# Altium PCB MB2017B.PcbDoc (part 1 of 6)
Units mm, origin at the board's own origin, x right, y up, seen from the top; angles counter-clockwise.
Board outline 148.19 x 169.19 mm, 4 copper layers (Top Layer, Mid Layer 1, Mid Layer 2, Bottom Layer), stack 1.498 mm thick; 458 components, 208 nets, 1223 pads, 6162 vias.
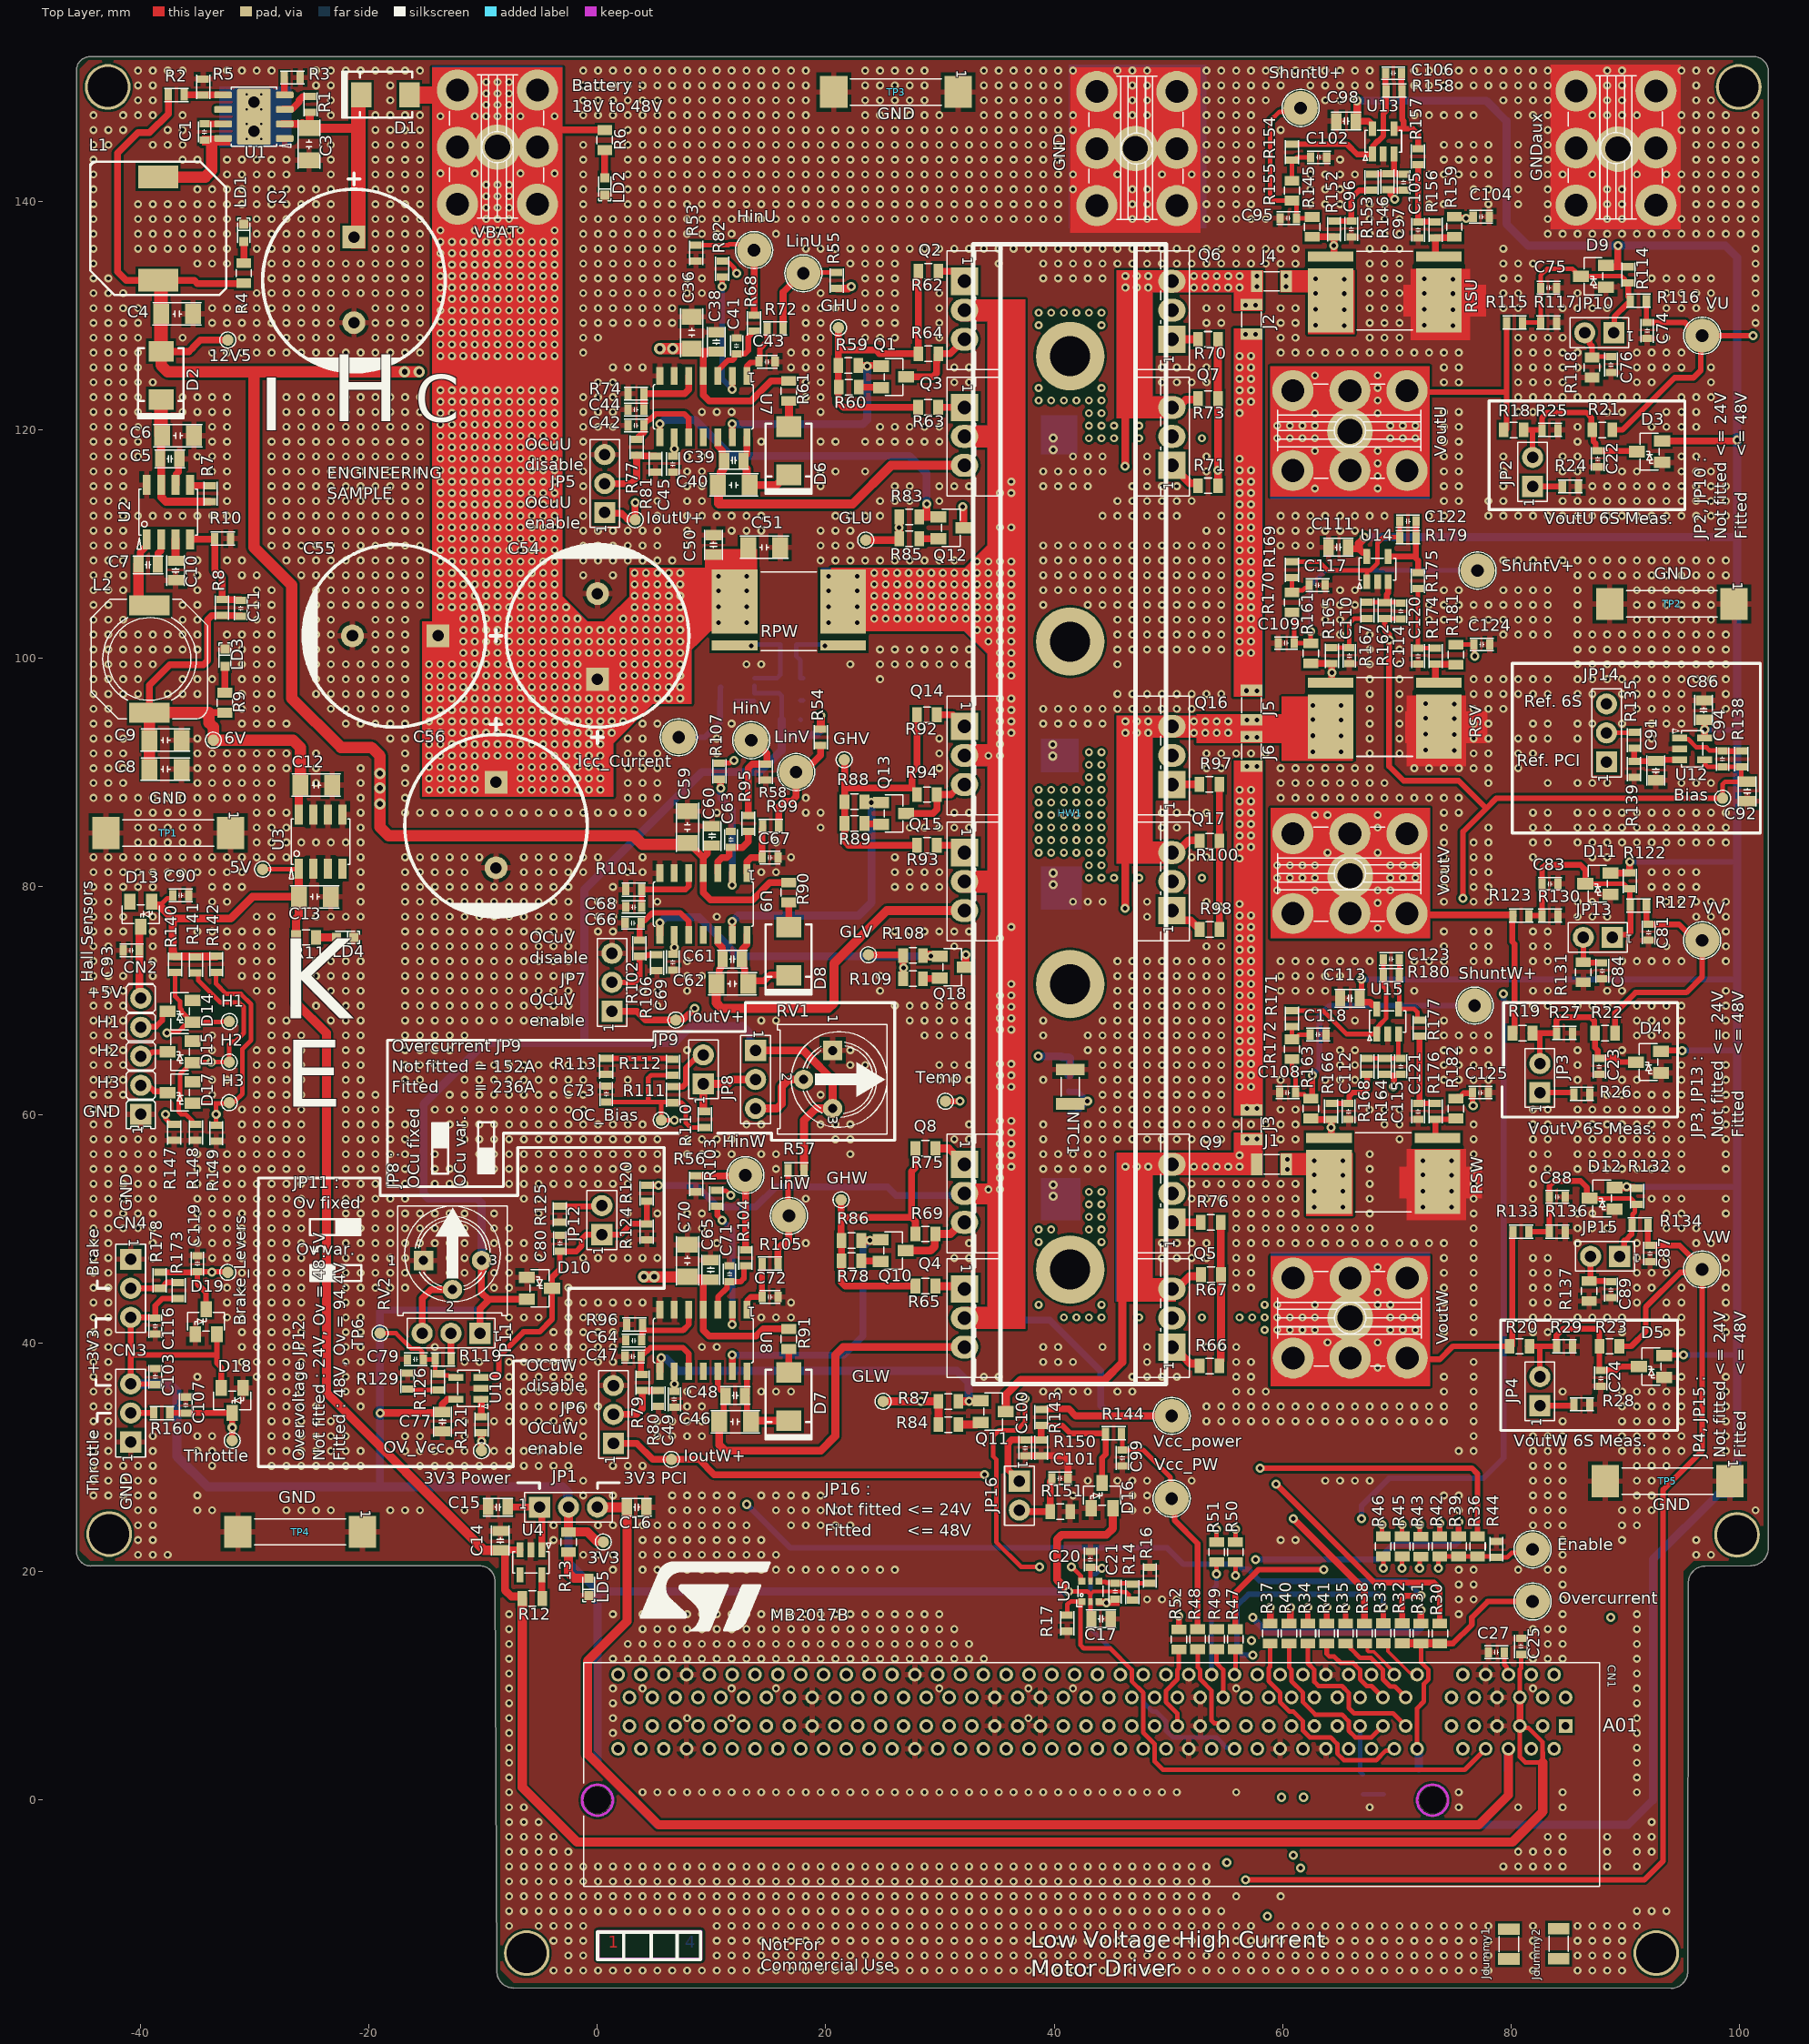
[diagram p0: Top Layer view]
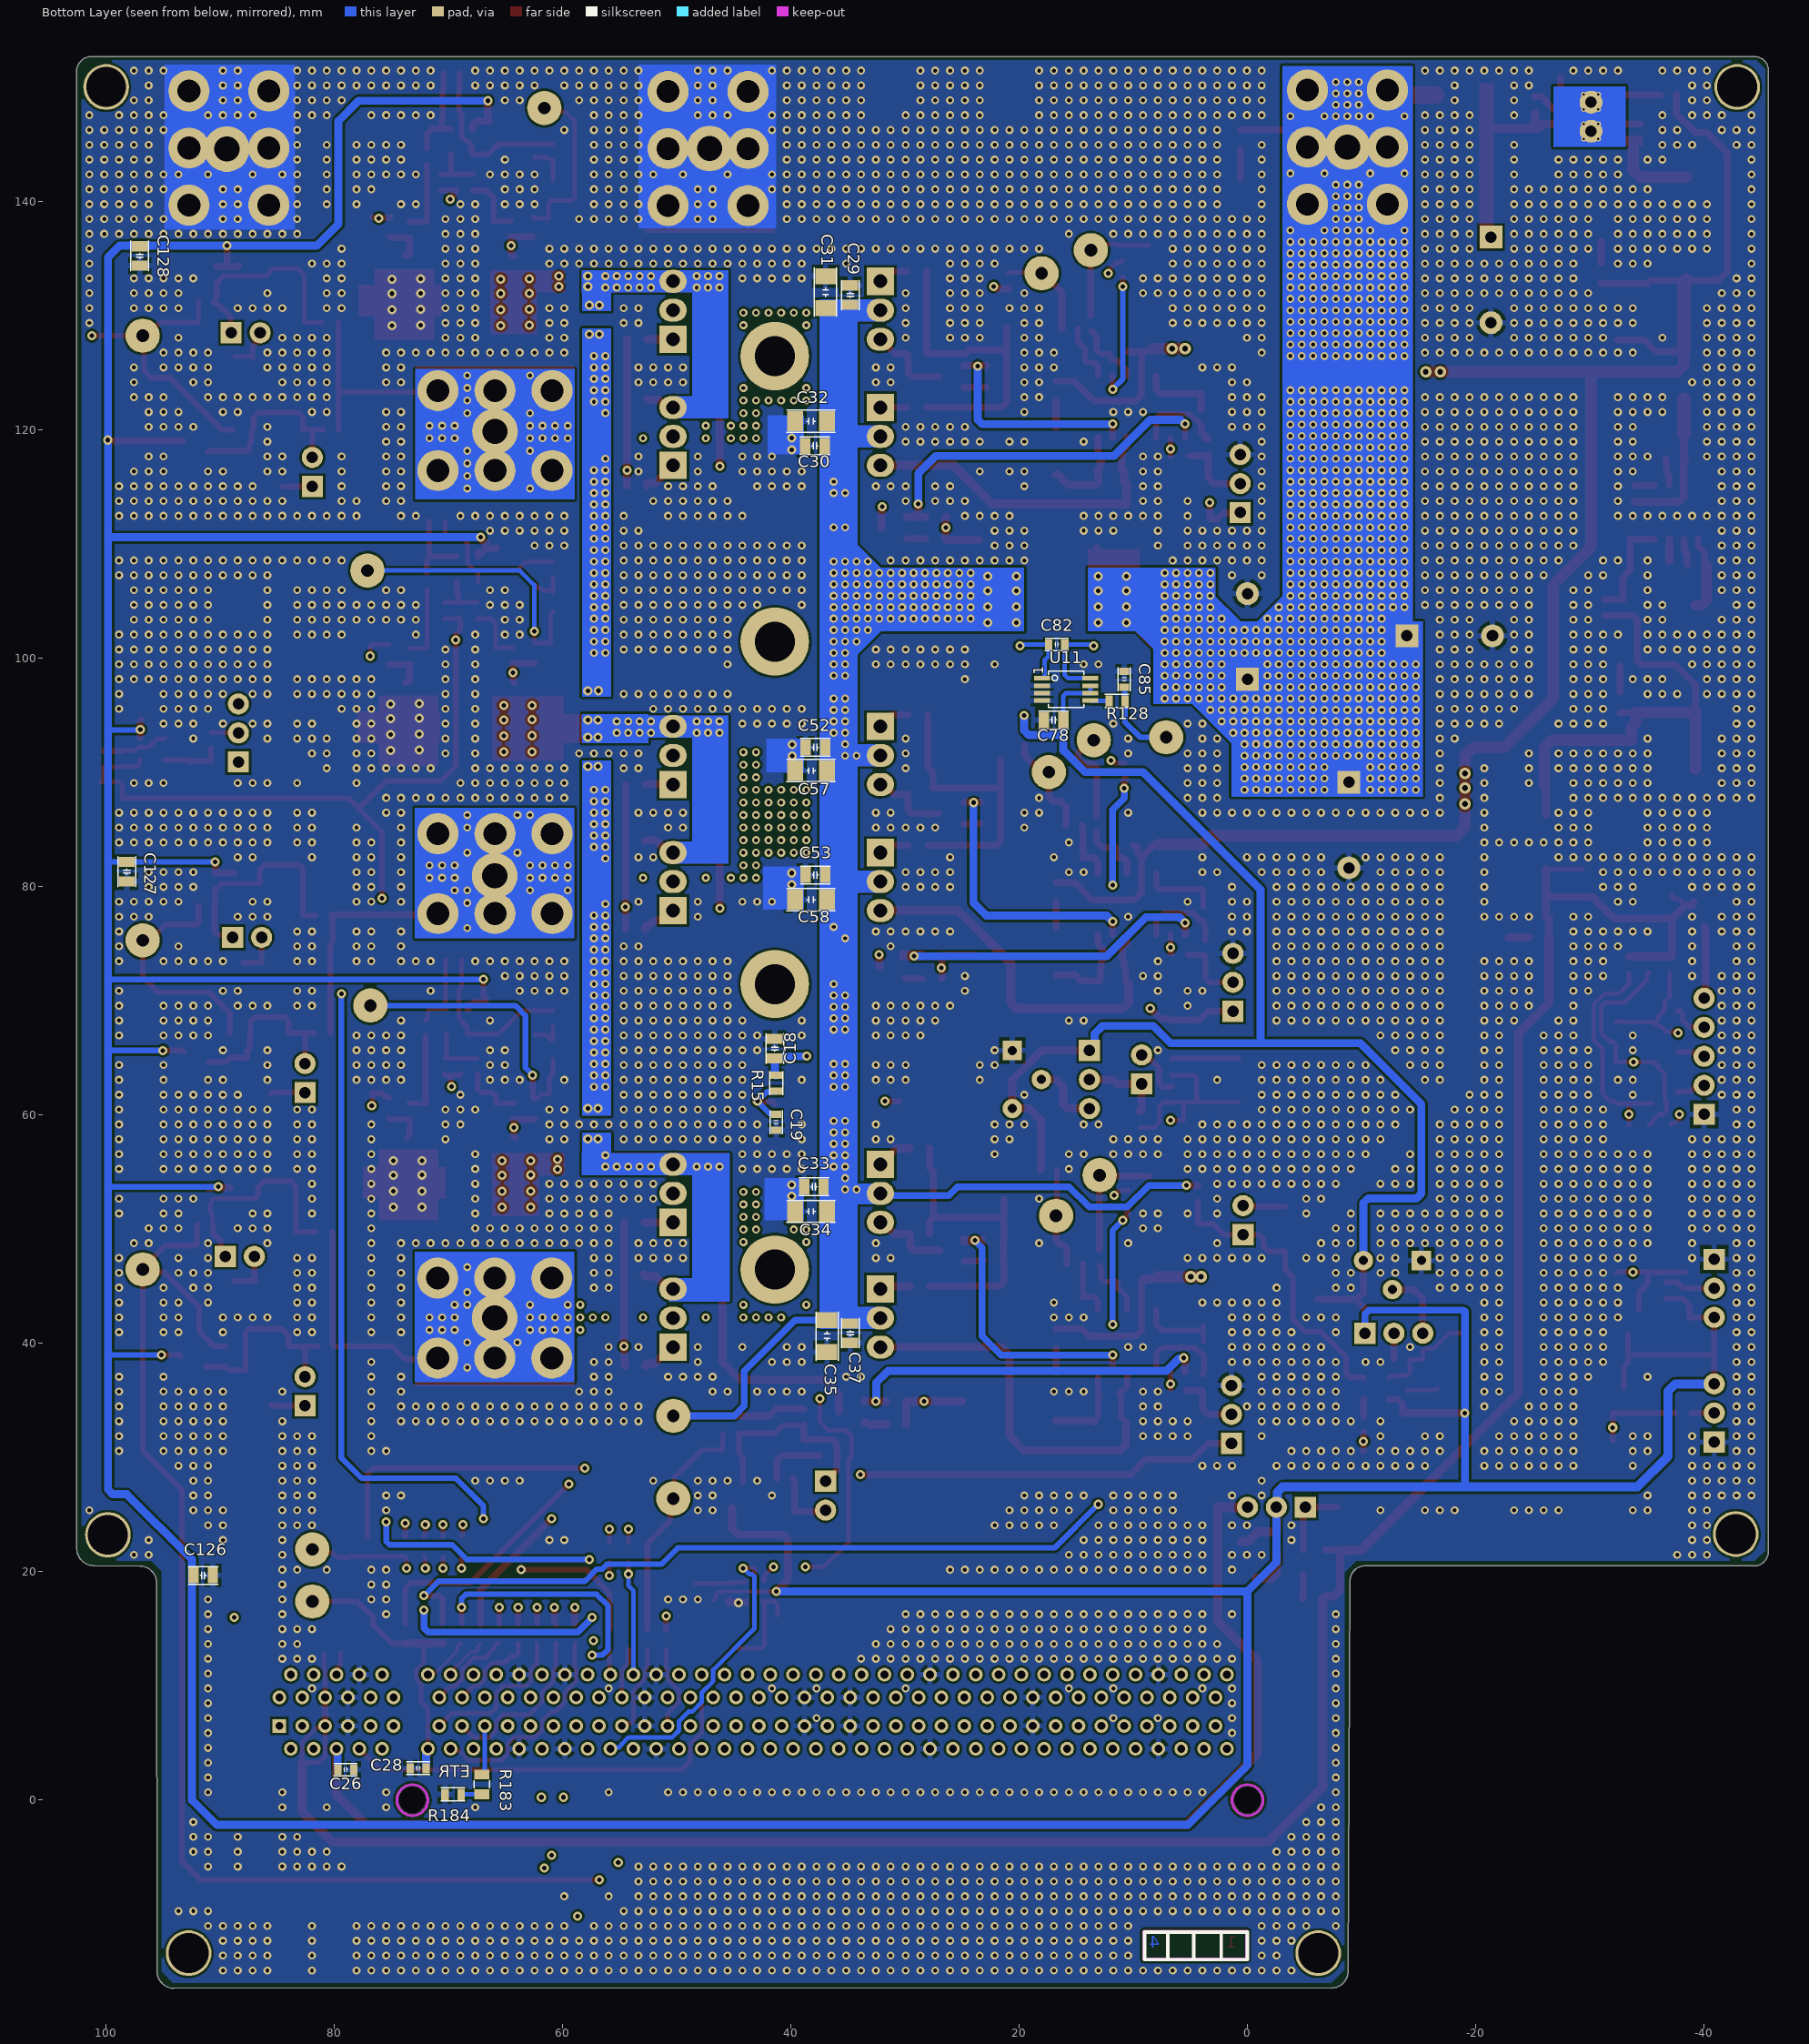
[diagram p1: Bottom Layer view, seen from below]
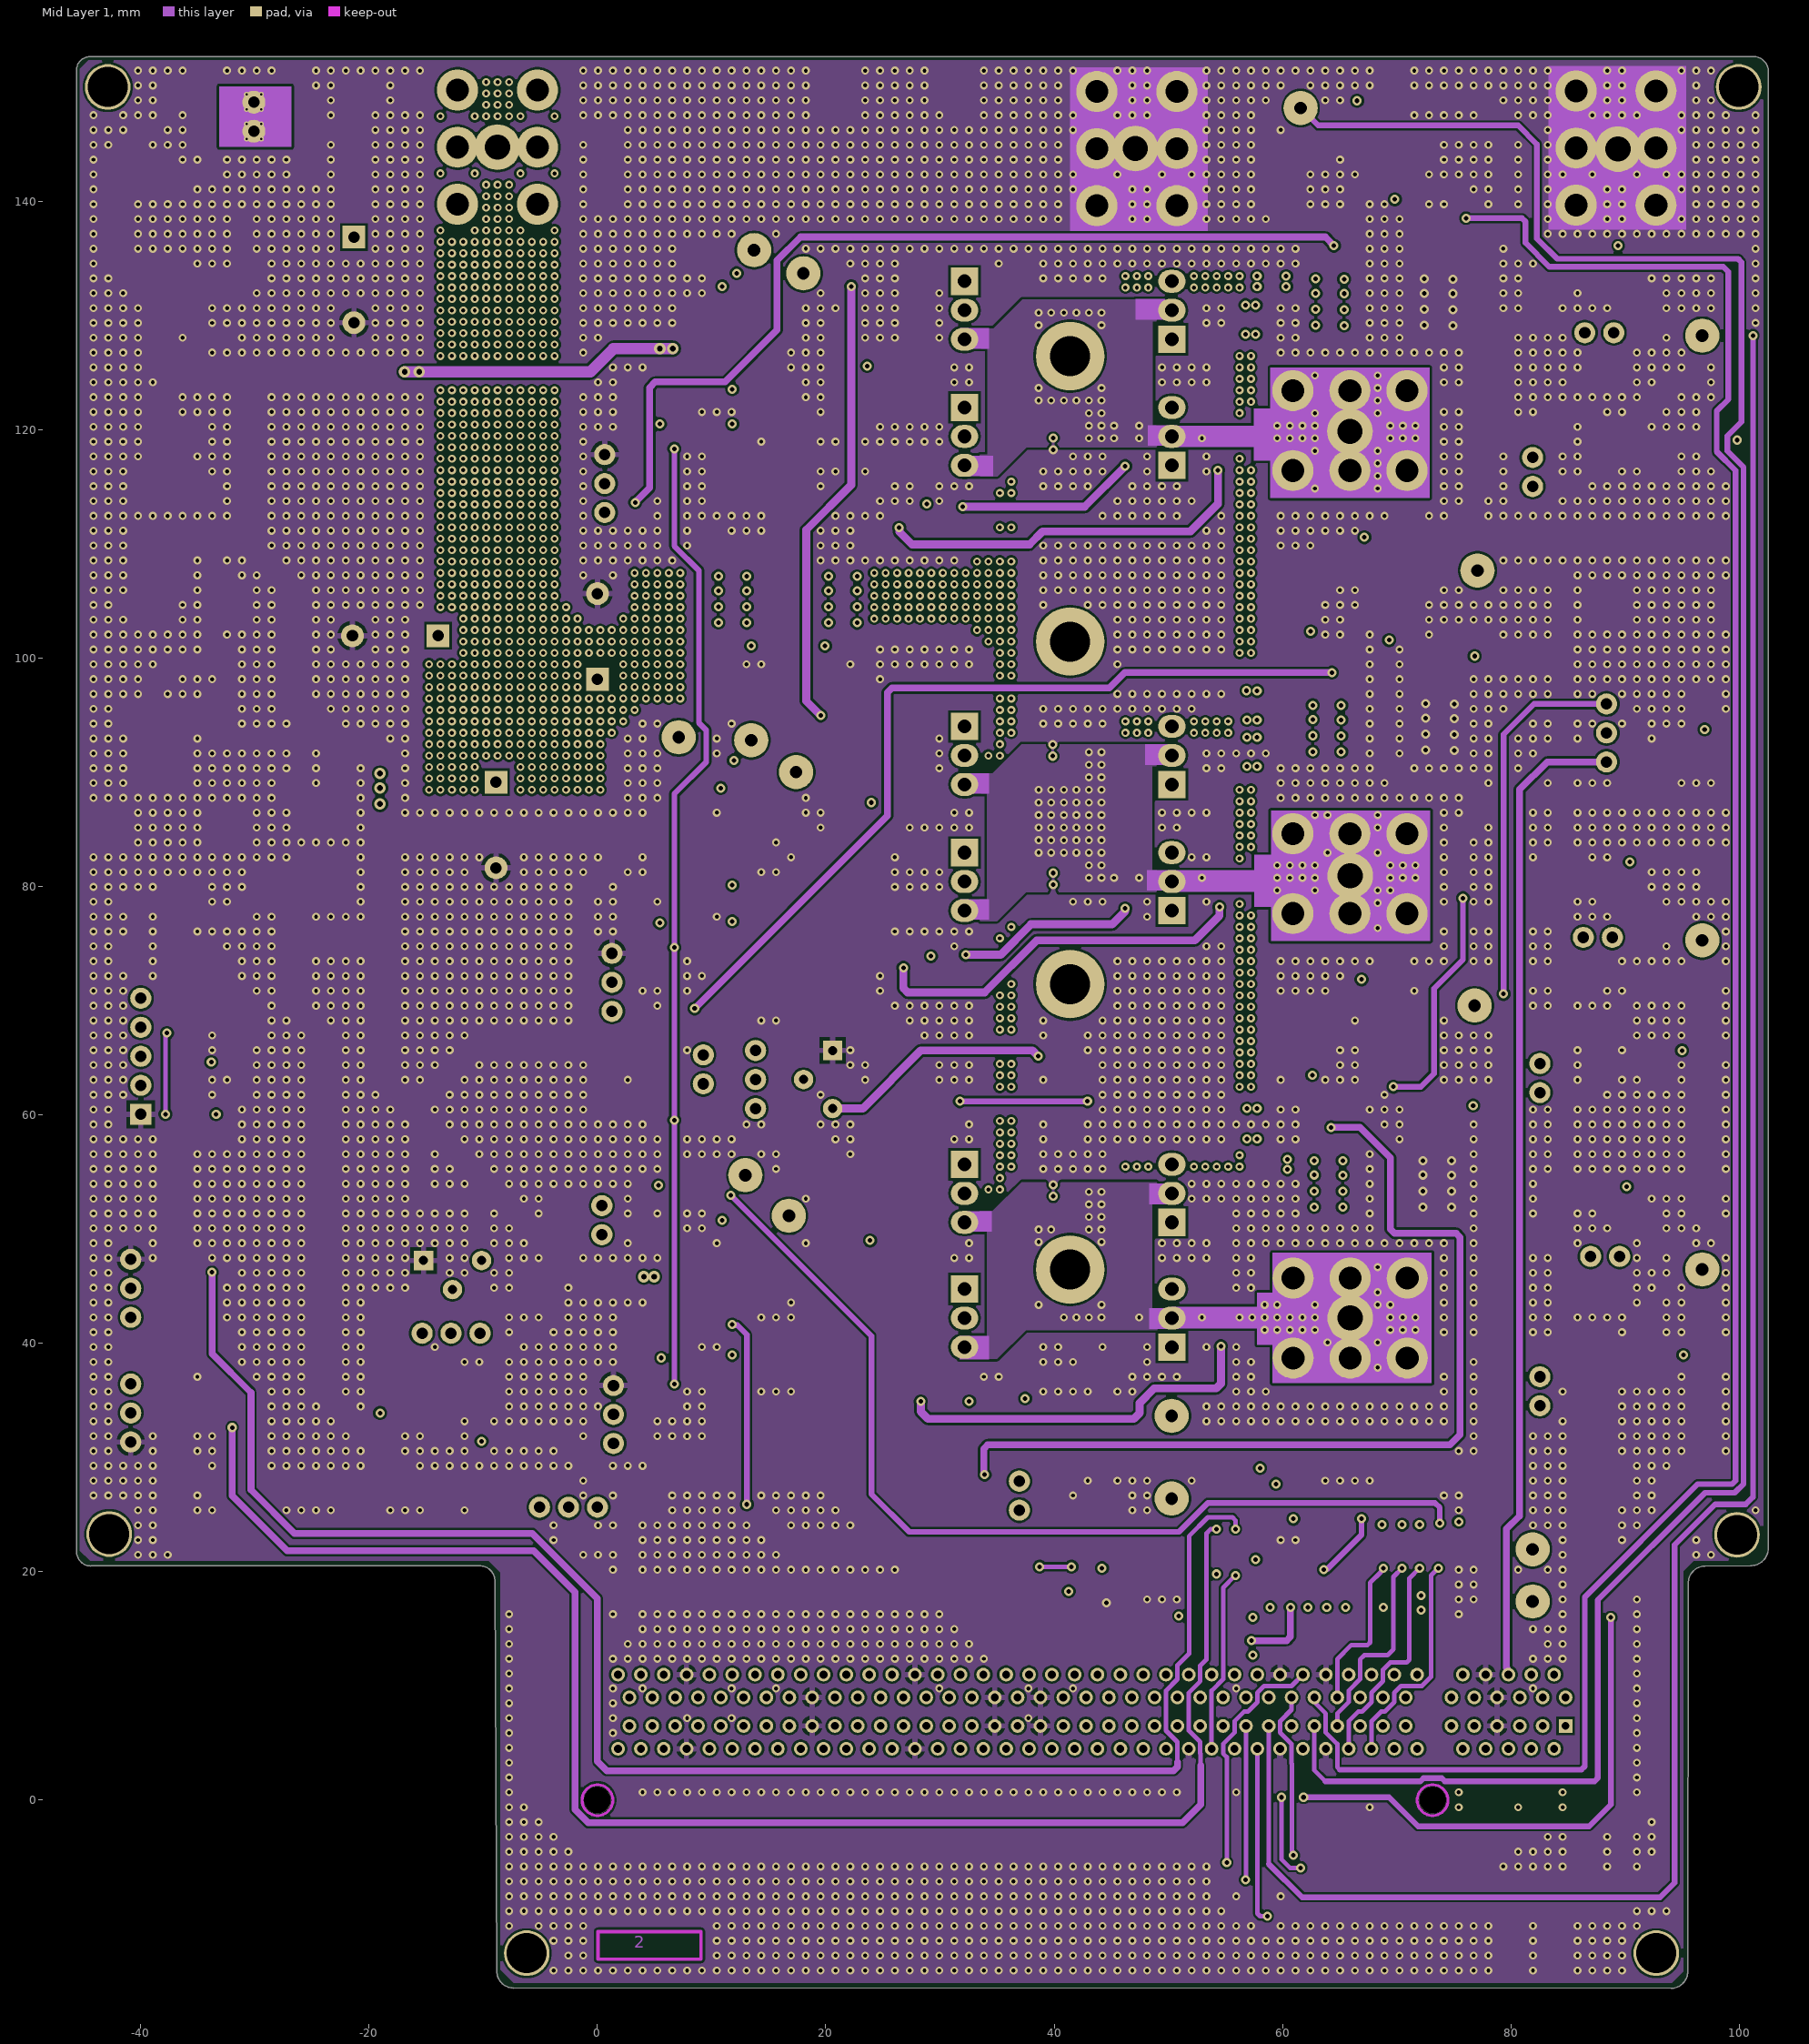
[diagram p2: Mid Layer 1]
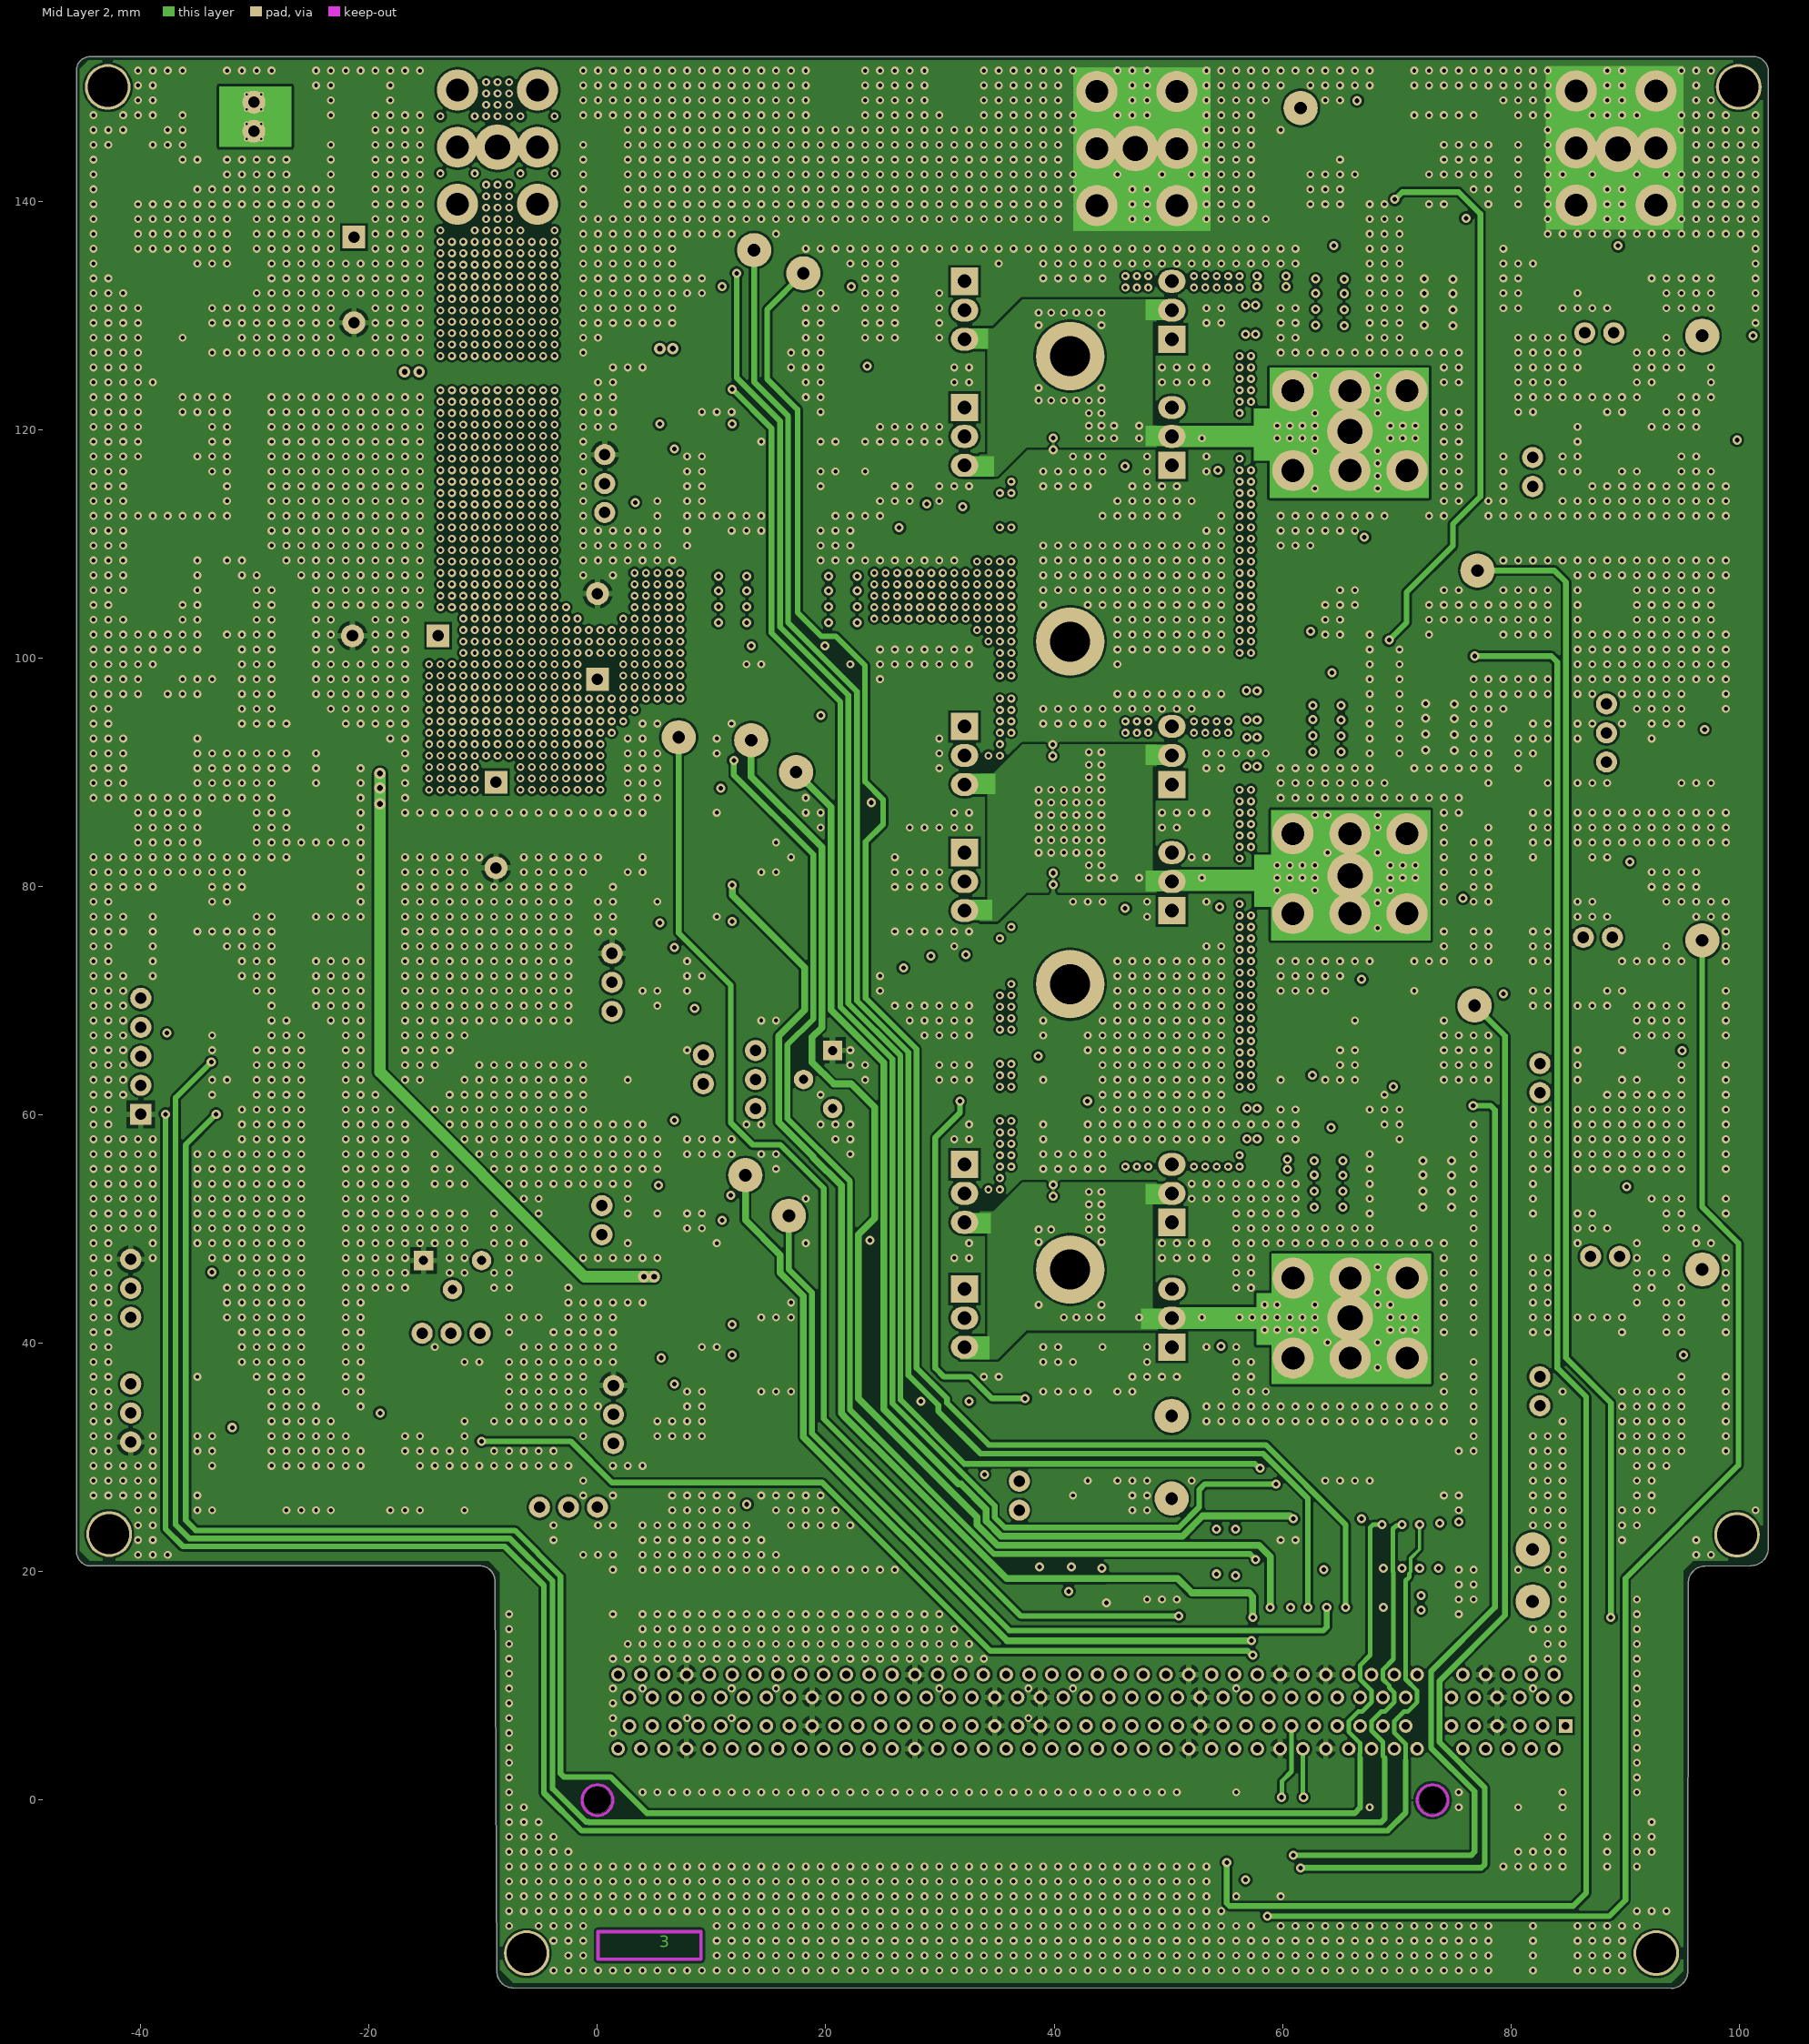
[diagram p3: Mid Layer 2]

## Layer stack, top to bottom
Top Solder: solder mask 0.015, Solder Resist, Dk 3.5
Top Layer: signal copper 0.07
Dielectric 2: prepreg 0.229, PP-006, Dk 4.1
Mid Layer 1: signal copper 0.07
Dielectric 1: dielectric 0.76, FR-4, Dk 4.8
Mid Layer 2: signal copper 0.07
Dielectric 3: prepreg 0.229, PP-006, Dk 4.1
Bottom Layer: signal copper 0.07
Bottom Solder: solder mask 0.015, Solder Resist, Dk 3.5

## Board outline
-10.318,20.524 cw(c-10.318,19.195) -8.988,19.195 -8.814,-14.986 ccw(c-7.339,-14.986) -7.339,-16.46 -7.339,-16.457 94.04,-16.48 ccw(c94.04,-15.018) 95.502,-15.018 95.553,19.022 cw(c97.026,19.022) 97.026,20.496 101.012,20.532 ccw(c101.012,22.083) 102.563,22.083 102.564,151.41 ccw(c101.265,151.41) 101.265,152.709 101.167,152.709 -44.481,152.694 ccw(c-44.481,151.544) -45.631,151.544 -45.631,21.762 ccw(c-44.377,21.762) -44.377,20.508 -44.362,20.524

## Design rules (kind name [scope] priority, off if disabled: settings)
Clearance [All] p1: gap=0.2 ignorepadtopadclearanceinfootprint=TRUE except(0: Arc-Text Arc-Hole Track-Text Track-Hole SMDPad-Text SMDPad-Hole THPad-Text THPad-Hole Via-Text Via-Hole Fill-Text Fill-Hole Poly-Text Poly-Hole Region-Text Region-Hole Text-Text Text-Hole)
ComponentClearance [All] p1: gap=0.2 collisioncheckmode=3 verticalgap=0.2 showdistances=FALSE
Height [All] p1: minheight=0 maxheight=80 prefheight=12.7
HoleSize [All] p1: absolutevalues=TRUE maxlimit=10 minlimit=0.025 maxpercent=80.000 minpercent=20.000
MinimumSolderMaskSliver [All] p1: minsoldermaskwidth=0.1
PlaneConnect [All] p1: planeconnectstyle=Relief reliefexpansion=0.508 reliefentries=4 reliefconductorwidth=0.5 reliefairgap=0.3
PolygonConnect PolygonConnect_via [IsVia] p1: connectstyle=Direct reliefconductorwidth=0.254 reliefentries=4 polygonreliefangle="90 Angle" airgapwidth=0.254
PolygonConnect [All] p2: connectstyle=Relief reliefconductorwidth=0.5 reliefentries=4 polygonreliefangle="90 Angle" airgapwidth=0.3
RoutingVias [All] p1: holewidth=0.4 width=0.8 viastyle="Through Hole" minholewidth=0.3 minwidth=0.8 maxholewidth=0.5 maxwidth=1
SilkToSilkClearance [All] p1: silktosilkclearance=0.05
SilkToSolderMaskClearance [IsPad] p1: minsilkscreentomaskgap=0.2 clearancetoexposedcopper=TRUE
SolderMaskExpansion [All] p1: expansion=0.102 istentingtop=FALSE
UnRoutedNet [All] p1: checkbadconnections=TRUE
Width [All] p1: maxlimit=10 minlimit=0.2 preferedwidth=0.4 minimp=50.000000 maximp=50.000000 favimp=50.000000
22 further rules are at their usual default settings.

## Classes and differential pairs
component class U_Sensors: Bias Brake_Levers C74 C75 C76 C77 C78 C79 C80 C81 C82 C83 C84 C85 C86 C87 C88 C89 C90 C91 C92 C93 C94 C95 C96 C97 C98 C99 C100 C101 C102 C103 C104 C105 C106 C107 C108 C109 C110 C111 C112 C113 C114 C115 C116 C117 C118 C119 C120 C121 C122 C123 C124 C125 CN2 CN3 CN4 D9 D10 D11 D12 D13 D14 D15 D16 D17 D18 D19 H1 H2 H3 Icc_Current JP10 JP11 JP12 JP13 JP14 JP15 JP16 OV_Vcc R114 R115 R116 R117 R118 R119 R120 R121 R122 R123 R124 R125 R126 R127 R128 R129 R130 R131 R132 R133 R134 R135 R136 R137 R138 R139 R140 R141 R142 R143 R144 R145 R146 R147 R148 R149 R150 R151 R152 R153 R154 R155 R156 R157 R158 R159 R160 R161 R162 R163 R164 R165 R166 R167 R168 R169 R170 R171 R172 R173 R174 R175 R176 R177 R178 R179 R180 R181 R182 RV2 ShuntU+ ShuntV+ ShuntW+ Throttle TP6 U10 U11 U12 U13 U14 U15 Vcc_PW VU VV VW
component class U_Sensors_2: C17 C18 C19 C20 C21 C22 C23 C24 D3 D4 D5 JP2 JP3 JP4 NTC1 R14 R15 R16 R17 R18 R19 R20 R21 R22 R23 R24 R25 R26 R27 R28 R29 Temp U5
component class U_Power_Stage: C29 C30 C31 C32 C33 C34 C35 C36 C37 C38 C39 C40 C41 C42 C43 C44 C45 C46 C47 C48 C49 C50 C51 C52 C53 C54 C55 C56 C57 C58 C59 C60 C61 C62 C63 C64 C65 C66 C67 C68 C69 C70 C71 C72 C73 D6 D7 D8 GHU GHV GHW GLU GLV GLW HinU HinV HinW HW1 IoutU+ IoutV+ IoutW+ J1 J2 J3 J4 J5 J6 Jdummy1 Jdummy2 JP5 JP6 JP7 JP8 JP9 LinU LinV LinW OC_Bias Q1 Q2 Q3 Q4 Q5 Q6 Q7 Q8 Q9 Q10 Q11 Q12 Q13 Q14 Q15 Q16 Q17 Q18 R59 R60 R61 R62 R63 R64 R65 R66 R67 R68 R69 R70 R71 R72 R73 R74 R75 R76 R77 R78 R79 R80 R81 R82 R83 R84 R85 R86 R87 R88 R89 R90 R91 R92 R93 R94 R95 R96 R97 R98 R99 R100 R101 R102 R103 R104 R105 R106 R107 R108 R109 R110 R111 R112 R113 RPW RSU RSV RSW RV1 TP1 TP2 TP3 TP4 TP5 U7 U8 U9 Vcc_power VoutU VoutV VoutW
component class U_Power_Supplies: 3V3 5V 6V 12V5 C1 C2 C3 C4 C5 C6 C7 C8 C9 C10 C11 C12 C13 C14 C15 C16 C126 C127 C128 D1 D2 GND GNDaux JP1 L1 L2 LD1 LD2 LD3 LD4 LD5 R1 R2 R3 R4 R5 R6 R7 R8 R9 R10 R11 R12 R13 U1 U2 U3 U4 VBAT
component class U_PCI_Connector: C25 C26 C27 C28 CN1 Enable Overcurrent R30 R31 R32 R33 R34 R35 R36 R37 R38 R39 R40 R41 R42 R43 R44 R45 R46 R47 R48 R49 R50 R51 R52 R53 R54 R55 R56 R57 R58 R183 R184

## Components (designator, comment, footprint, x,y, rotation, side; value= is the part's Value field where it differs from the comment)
3V3 "Test Point" TP_SMD_1MM 0.508,22.606 r180 top value="Test Point 1mm"
5V "Test Point" TP_SMD_1MM -29.337,81.534 r90 top value="Test Point 1mm"
6V "Test Point" TP_SMD_1MM -33.655,92.837 r90 top value="Test Point 1mm"
12V5 "Test Point" TP_SMD_1MM -32.385,127.889 r90 top value="Test Point 1mm"
Bias "Test Point" TP_SMD_1MM 98.552,87.757 r270 top value="Test Point 1mm"
Brake_Levers "Test Point" TP_SMD_1MM -32.385,46.228 r90 top value="Test Point 1mm"
C1 "Capacitor" C0603_H0P8 -34.417,146.115 r90 top value=2.2nF
C2 "Cap_POL_TANA" CPOL_TDK_B41858C9227M000_H25 -21.336,136.906 r270 top value=220uF
C3 "Capacitor" C1206_H1P6 -25.273,145.037 r90 top value=1uF
C4 "Capacitor" C1206_H1P6 -36.827,130.175 r180 top value=47uF
C5 "Capacitor" C0805_H0P85 -37.465,117.475 r180 top value=1uF
C6 "Capacitor" C1206_H1P6 -36.757,119.511 r180 top value=10uF
C7 "Capacitor" C0805_H0P85 -39.37,108.204 r0 top value=100nF
C8 "Capacitor" C1206_H1P6 -37.843,90.297 r180 top value=10uF
C9 "Capacitor" C1206_H1P6 -37.843,92.837 r180 top value=22uF
C10 "Capacitor" C0805_H0P85 -36.957,107.696 r90 top value=1uF
C11 "Capacitor" C0603 -31.242,104.394 r270 top value=10pF
C12 "Capacitor" C1206_H1P6 -24.635,88.9 r180 top value=10uF
C13 "Capacitor" C1206_H1P6 -24.762,79.121 r180 top value=10uF
C14 "Capacitor" C0805_H0P85 -8.509,22.733 r270 top value=1uF
C15 "Capacitor" C0805_H0P85 -8.724,25.654 r0 top value=1uF
C16 "Capacitor" C0805_H0P85 3.429,25.654 r180 top value=1uF
C17 "Capacitor" C0805_H0P85 44.108,15.875 r180 top value=1uF
C18 "Capacitor" C0805_H0P85 41.402,65.825 r270 bottom value=1uF
C19 "Capacitor" C0603 41.275,59.371 r90 bottom value=4.7nF
C20 "Capacitor" C0603 43.18,21.082 r270 top value=4.7nF
C21 "Capacitor" C0603 45.339,18.288 r90 top value=100nF
C22 "Capacitor" C0603 87.63,117.475 r90 top value=10pF
C23 "Capacitor" C0603 87.757,64.262 r90 top value=10pF
C24 "Capacitor" C0603 87.884,36.957 r90 top value=10pF
C25 "Capacitor" C0603 80.899,13.462 r90 top value=100nF
C26 "Capacitor" C0603 78.994,2.667 r180 bottom value=100nF
C27 "Capacitor" C0603 78.74,12.954 r180 top value=100nF
C28 "Capacitor" C0603 72.644,2.794 r0 bottom value=100nF
C29 "Capacitor" C0805 34.798,131.826 r90 bottom value=100nF
C30 "Capacitor" C0805 37.885,118.618 r0 bottom value=100nF
C31 "Capacitor" C1206_H1P6 36.957,132.08 r90 bottom value=1uF
C32 "Capacitor" C1206_H1P6 38.227,120.777 r0 bottom value=1uF
C33 "Capacitor" C0805 37.973,53.721 r0 bottom value=100nF
C34 "Capacitor" C1206_H1P6 38.227,51.562 r0 bottom value=1uF
C35 "Capacitor" C1206_H1P6 36.83,40.64 r270 bottom value=1uF
C36 "Capacitor" C1206_H1P25 8.255,128.527 r270 top value=4.7uF
C37 "Capacitor" C0805 34.798,40.894 r270 bottom value=100nF
C38 "Capacitor" C0805_H0P85 10.414,127.723 r270 top value=100nF
C39 "Capacitor" C0805_H0P85 11.938,117.348 r0 top value=100nF
C40 "Capacitor" C1206_H1P15 11.938,115.189 r0 top value=1uF
C41 "Capacitor" C0603_H0P8 12.192,127.381 r270 top value=100pF
C42 "Capacitor" C0603 3.364,120.396 r180 top value=10nF
C43 "Capacitor" C0603_H0P8 14.859,125.984 r180 top value=100pF
C44 "Capacitor" C0603 3.364,121.793 r0 top value=100nF
C45 "Capacitor" C0603 6.604,117.029 r90 top value=100nF
C46 "Capacitor" C1206_H1P15 12.065,33.147 r0 top value=1uF
C47 "Capacitor" C0603 3.113,38.862 r180 top value=10nF
C48 "Capacitor" C0805_H0P85 12.065,35.433 r0 top value=100nF
C49 "Capacitor" C0603 6.731,35.117 r90 top value=100nF
C50 "Capacitor" C0805 10.16,109.943 r90 top value=100nF
C51 "Capacitor" C1206_H1P6 14.608,109.728 r0 top value=1uF
C52 "Capacitor" C0805 37.846,92.202 r0 bottom value=100nF
C53 "Capacitor" C0805 37.846,81.026 r0 bottom value=100nF
C54 "Cap_POL_TANA" CPOL_TDK_B41858C9227M000_H25 0,98.171 r90 top value=220uF
C55 "Cap_POL_TANA" CPOL_TDK_B41858C9227M000_H25 -13.97,101.981 r180 top value=220uF
C56 "Cap_POL_TANA" CPOL_TDK_B41858C9227M000_H25 -8.89,89.154 r270 top value=220uF
C57 "Capacitor" C1206_H1P6 38.227,90.17 r0 bottom value=1uF
C58 "Capacitor" C1206_H1P6 38.227,78.867 r0 bottom value=1uF
C59 "Capacitor" C1206_H1P25 7.874,85.214 r270 top value=4.7uF
C60 "Capacitor" C0805_H0P85 10.033,84.455 r270 top value=100nF
C61 "Capacitor" C0805_H0P85 11.811,73.66 r0 top value=100nF
C62 "Capacitor" C1206_H1P15 11.814,71.501 r0 top value=1uF
C63 "Capacitor" C0603_H0P8 11.684,84.136 r270 top value=100pF
C64 "Capacitor" C0603 3.175,40.259 r0 top value=100nF
C65 "Capacitor" C0805_H0P85 9.906,46.443 r270 top value=100nF
C66 "Capacitor" C0603 3.113,76.835 r180 top value=10nF
C67 "Capacitor" C0603_H0P8 15.113,82.55 r180 top value=100pF
C68 "Capacitor" C0603 3.175,78.232 r0 top value=100nF
C69 "Capacitor" C0603 6.604,73.406 r90 top value=100nF
C70 "Capacitor" C1206_H1P25 7.874,47.244 r270 top value=4.7uF
C71 "Capacitor" C0603_H0P8 11.557,46.101 r270 top value=100pF
C72 "Capacitor" C0603_H0P8 15.113,44.069 r180 top value=100pF
C73 "Capacitor" C0603 0.762,61.849 r270 top value=100nF
C74 "Capacitor" C0603 91.948,128.716 r90 top value=100pF
C75 "Capacitor" C0603 83.312,132.461 r180 top value=33nF
C76 "Capacitor" C0603 88.773,125.73 r90 top value=33nF
C77 "Capacitor" C0805_H0P85 -13.589,33.147 r90 top value=1uF
C78 "Capacitor" C0805_H0P85 16.979,94.615 r180 bottom value=1uF
C79 "Capacitor" C0603 -15.94,38.608 r180 top value=100nF
C80 "Capacitor" C0603 -3.302,48.768 r270 top value=1nF
C81 "Capacitor" C0603 92.075,76.008 r90 top value=100pF
C82 "Capacitor" C0603 16.699,101.219 r180 bottom value=10nF
C83 "Capacitor" C0603 83.439,80.264 r180 top value=33nF
C84 "Capacitor" C0603 88.011,72.644 r90 top value=33nF
C85 "Capacitor" C0603 10.795,98.171 r270 bottom value=10nF
C86 "Capacitor" C0805_H0P85 96.901,95.465 r270 top value=1uF
C87 "Capacitor" C0603 92.202,47.879 r90 top value=100pF
C88 "Capacitor" C0603 84.074,52.832 r180 top value=33nF
C89 "Capacitor" C0603 88.773,44.704 r90 top value=33nF
C90 "Capacitor" C0603 -36.511,79.248 r0 top value=100nF
C91 "Capacitor" C0805_H0P85 92.71,90.17 r90 top value=1uF
C92 "Capacitor" C0805_H0P85 100.711,88.353 r90 top value=1uF
C93 "Capacitor" C0603 -40.832,74.422 r180 top value=100nF
C94 "Capacitor" C0603 98.552,91.186 r270 top value=10nF
C95 "Capacitor" C0603 60.514,138.557 r180 top value=1nF
C96 "Capacitor" C0603 66.04,137.603 r270 top value=1nF
C97 "Capacitor" C0603 70.612,141.705 r270 top value=10pF
C98 "Capacitor" C0805_H0P85 65.571,147.066 r0 top value=1uF
C99 "Capacitor" C0603 45.974,29.972 r90 top value=100pF
C100 "Capacitor" C0603 37.465,30.861 r90 top value=10nF
C101 "Capacitor" C0603 40.513,28.194 r180 top value=10nF
C102 "Capacitor" C0603 63.181,143.891 r180 top value=100pF
C103 "Capacitor" C0603 -38.735,37.084 r90 top value=100nF
C104 "Capacitor" C0603 77.408,138.684 r0 top value=1nF
C105 "Capacitor" C0603 71.882,137.541 r90 top value=1nF
C106 "Capacitor" C0603 69.723,151.257 r0 top value=10pF
C107 "Capacitor" C0603 -36.068,34.609 r90 top value=100nF
C108 "Capacitor" C0603 60.452,61.976 r180 top value=1nF
C109 "Capacitor" C0603 60.325,101.346 r180 top value=1nF
C110 "Capacitor" C0603 65.859,100.23 r270 top value=1nF
C111 "Capacitor" C0805_H0P85 64.897,109.728 r0 top value=1uF
C112 "Capacitor" C0603 65.786,60.325 r270 top value=1nF
C113 "Capacitor" C0805_H0P85 65.913,70.231 r0 top value=1uF
C114 "Capacitor" C0603 70.358,104.14 r270 top value=10pF
C115 "Capacitor" C0603 70.358,64.262 r270 top value=10pF
C116 "Capacitor" C0603 -38.735,41.529 r270 top value=100nF
C117 "Capacitor" C0603 63.054,106.426 r180 top value=100pF
C118 "Capacitor" C0603 63.119,67.056 r180 top value=100pF
C119 "Capacitor" C0603 -35.052,46.99 r90 top value=100nF
C120 "Capacitor" C0603 71.882,100.203 r90 top value=1nF
C121 "Capacitor" C0603 71.882,60.325 r90 top value=1nF
C122 "Capacitor" C0603 70.993,112.014 r0 top value=10pF
C123 "Capacitor" C0603 69.531,73.66 r0 top value=10pF
C124 "Capacitor" C0603 77.47,101.219 r180 top value=1nF
C125 "Capacitor" C0603 77.343,61.976 r180 top value=1nF
C126 "Capacitor" C0805_H0P85 91.479,19.685 r0 bottom value=1uF
C127 "Capacitor" C0805_H0P85 98.171,81.319 r90 bottom value=1uF
C128 "Capacitor" C0805_H0P85 97.028,135.255 r90 bottom value=1uF
CN1 "PCIE-164-02-X-D-RA" CON_SAMTEC_PCIE-164-02-X-D-RA 43.3,2.25 r0 top locked value=Socket_PCIE-164-02-S-D-RA
CN2 "Header 5x1" CON_SAMTEC_TSW-105-07-X-S -40.005,65.151 r90 top
CN3 "Header 3x1" CON_SAMTEC_TSW-103-07-F-S -40.894,33.909 r90 top
CN4 "Header 3x1" CON_SAMTEC_TSW-103-07-F-S -40.894,44.831 r270 top
D1 "DIODE_1K_2A" DIO_SMB_1K_2A -20.701,149.352 r0 top value=STTH2R02U
D2 "DIODE_1K_2A" DIO_SMB_1K_2A -38.227,122.682 r90 top value=STTH2R02U
D3 "DIODE_3P_DUAL_SERIES" DIO_SOT23 92.159,118.11 r90 top value=BAT54SFILM
D4 "DIODE_3P_DUAL_SERIES" DIO_SOT23 92.075,64.643 r90 top value=BAT54SFILM
D5 "DIODE_3P_DUAL_SERIES" DIO_SOT23 92.329,37.973 r90 top value=BAT54SFILM
D6 "DIODE_1K_2A" DIO_SMB_1K_2A 16.764,116.078 r90 top value=STTH2R02U
D7 "DIODE_1K_2A" DIO_SMB_1K_2A 16.764,33.245 r90 top value=STTH2R02U
D8 "DIODE_1K_2A" DIO_SMB_1K_2A 16.764,72.234 r90 top value=STTH2R02U
D9 "DIODE_3P_DUAL_SERIES" DIO_SOT23 87.249,133.477 r90 top value=BAT54SFILM
D10 "DIODE_3P_DUAL_SERIES" DIO_SOT23 -5.08,44.831 r270 top value=BAT54SFILM
D11 "DIODE_3P_DUAL_SERIES" DIO_SOT23 87.63,80.264 r90 top value=BAT54SFILM
D12 "DIODE_3P_DUAL_SERIES" DIO_SOT23 88.011,52.705 r90 top value=BAT54SFILM
D13 "DIODE_SOT23" DIO_SOT23 -40.005,77.597 r180 top value=BAT54FILM
D14 "DIODE_SOT23" DIO_SOT23 -36.576,69.088 r90 top value=BAT54FILM
D15 "DIODE_SOT23" DIO_SOT23 -36.576,65.532 r90 top value=BAT54FILM
D16 "DIODE_3P_DUAL_SERIES" DIO_SOT23 44.196,26.67 r0 top value=BAT54SFILM
D17 "DIODE_SOT23" DIO_SOT23 -36.576,61.976 r90 top value=BAT54FILM
D18 "DIODE_3P_DUAL_SERIES" DIO_SOT23 -32.004,35.009 r180 top value=BAT54SFILM
D19 "DIODE_3P_DUAL_SERIES" DIO_SOT23 -34.29,41.91 r0 top value=BAT54SFILM
Enable "Test_pin_conn_black - NOT CONNECTED" TP_PTH-1P02MM_TEST-TERMINAL_RS_101-2391_BLACK 81.915,21.971 r0 top value=20-2137
GHU "Test Point" TP_SMD_1MM 21.105,128.967 r90 top value="Test Point 1mm"
GHV "Test Point" TP_SMD_1MM 21.613,91.121 r90 top value="Test Point 1mm"
GHW "Test Point" TP_SMD_1MM 21.336,52.578 r90 top value="Test Point 1mm"
GLU "Test Point" TP_SMD_1MM 23.495,110.363 r90 top value="Test Point 1mm"
GLV "Test Point" TP_SMD_1MM 23.729,74.037 r90 top value="Test Point 1mm"
GLW "Test Point" TP_SMD_1MM 25.019,34.925 r90 top value="Test Point 1mm"
GND "CON_M4_SNAP_IN_THR_KEYSTONE_7798" CON_KEYSTONE_M4-SNAP_7798 47.244,144.653 r90 top value="TERM SCREW M4 PCB 30A"
GNDaux "CON_M4_SNAP_IN_THR_KEYSTONE_7798" CON_KEYSTONE_M4-SNAP_7798 89.225,144.7 r90 top value="TERM SCREW M4 PCB 30A"
H1 "Test Point" TP_SMD_1MM -32.258,68.199 r90 top value="Test Point 1mm"
H2 "Test Point" TP_SMD_1MM -32.258,64.643 r180 top value="Test Point 1mm"
H3 "Test Point" TP_SMD_1MM -32.258,61.087 r180 top value="Test Point 1mm"
HinU "Test_pin_conn_black - NOT CONNECTED" TP_PTH-1P02MM_TEST-TERMINAL_RS_101-2391_BLACK 13.716,135.763 r0 top value=20-2137
HinV "Test_pin_conn_black - NOT CONNECTED" TP_PTH-1P02MM_TEST-TERMINAL_RS_101-2391_BLACK 13.462,92.837 r0 top value=20-2137
HinW "Test_pin_conn_black - NOT CONNECTED" TP_PTH-1P02MM_TEST-TERMINAL_RS_101-2391_BLACK 12.954,54.737 r0 top value=20-2137
HW1 "SK664100SA" MISC_Fischer_Elektronik_SK664100SA 41.402,46.473 r90 top
Icc_Current "Test_pin_conn_black - NOT CONNECTED" TP_PTH-1P02MM_TEST-TERMINAL_RS_101-2391_BLACK 7.112,93.091 r90 top value=20-2137
IoutU+ "Test Point" TP_SMD_1MM 3.302,112.141 r90 top value="Test Point 1mm"
IoutV+ "Test Point" TP_SMD_1MM 6.858,68.326 r90 top value="Test Point 1mm"
IoutW+ "Test Point" TP_SMD_1MM 6.477,29.845 r90 top value="Test Point 1mm"
J1 "Resistor" MISC_JUMPER_1206_H0P55 59.048,55.688 r180 top value=TLRZ2BTTD
J2 "Resistor" MISC_JUMPER_1206_H0P55 57.3,129.699 r90 top value=TLRZ2BTTD
J3 "Resistor" MISC_JUMPER_1206_H0P55 57.3,59.147 r90 top value=TLRZ2BTTD
J4 "Resistor" MISC_JUMPER_1206_H0P55 59.048,133.031 r180 top value=TLRZ2BTTD
J5 "Resistor" MISC_JUMPER_1206_H0P55 57.3,95.917 r270 top value=TLRZ2BTTD
J6 "Resistor" MISC_JUMPER_1206_H0P55 57.3,91.853 r90 top value=TLRZ2BTTD
Jdummy1 "Resistor" MISC_JUMPER_1206_H0P55 79.829,-12.608 r270 top value=TLRZ2BTTD
Jdummy2 "Resistor" MISC_JUMPER_1206_H0P55 84.201,-12.573 r270 top value=TLRZ2BTTD
JP1 "Jumper_Header 3x1 Fitted 1-2" CON_SAMTEC_TSW-103-07-F-S -2.54,25.654 r0 top value="Header 3x1"
JP2 "Jumper_Header 2x1" CON_SAMTEC_TSW-102-07-G-S 81.915,116.332 r90 top value="Header 2x1"
JP3 "Jumper_Header 2x1" CON_SAMTEC_TSW-102-07-G-S 82.55,63.246 r90 top value="Header 2x1"
JP4 "Jumper_Header 2x1" CON_SAMTEC_TSW-102-07-G-S 82.55,35.814 r90 top value="Header 2x1"
JP5 "Jumper_Header 3x1 Fitted 1-2" CON_SAMTEC_TSW-103-07-F-S 0.635,115.316 r90 top value="Header 3x1"
JP6 "Jumper_Header 3x1 Fitted 1-2" CON_SAMTEC_TSW-103-07-F-S 1.397,33.782 r90 top value="Header 3x1"
JP7 "Jumper_Header 3x1 Fitted 1-2" CON_SAMTEC_TSW-103-07-F-S 1.27,71.628 r90 top value="Header 3x1"
JP8 "Jumper_Header 3x1 Fitted 1-2" CON_SAMTEC_TSW-103-07-F-S 13.843,63.119 r270 top value="Header 3x1"
JP9 "Jumper_Header 2x1" CON_SAMTEC_TSW-102-07-G-S 9.271,64.008 r90 top value="Header 2x1"
JP10 "Jumper_Header 2x1" CON_SAMTEC_TSW-102-07-G-S 87.757,128.524 r180 top value="Header 2x1"
JP11 "Jumper_Header 3x1 Fitted 1-2" CON_SAMTEC_TSW-103-07-F-S -12.827,40.894 r180 top value="Header 3x1"
JP12 "Jumper_Header 2x1" CON_SAMTEC_TSW-102-07-G-S 0.381,50.8 r90 top value="Header 2x1"
JP13 "Jumper_Header 2x1" CON_SAMTEC_TSW-102-07-G-S 87.63,75.565 r180 top value="Header 2x1"
JP14 "Jumper_Header 3x1 Fitted 1-2" CON_SAMTEC_TSW-103-07-F-S 88.392,93.472 r90 top value="Header 3x1"
JP15 "Jumper_Header 2x1" CON_SAMTEC_TSW-102-07-G-S 88.265,47.625 r180 top value="Header 2x1"
JP16 "Jumper_Header 2x1" CON_SAMTEC_TSW-102-07-G-S 36.957,26.67 r270 top value="Header 2x1"
L1 "INDUCTOR_POWER_WINDING" IND_WURTH_7447714680 -38.481,142.113 r270 top value=68uH
L2 "INDUCTOR_POWER_WINDING" IND_COILCRAFT_MSS1038T-333MLC -39.243,99.949 r0 top value=33uH
LD1 "LED_green" LED_0603_VISHAY_VLMTG1300-GS08_GREEN_1A2K_H0P8 -30.988,137.275 r90 top value=Green
LD2 "LED_red" LED_0603_VISHAY_VLMS1300-GS08_RED_1A2K_H0P8 0.635,141.339 r270 top value=Red
LD3 "LED_orange" LED_0603_VISHAY_VLMO1300-GS08_ORANGE_1A2K_H0P8 -32.639,100.064 r90 top value=Orange
LD4 "LED_red" LED_0603_VISHAY_VLMS1300-GS08_RED_1A2K_H0P8 -22.11,75.565 r0 top value=Red
LD5 "LED_blue" LED_0603_VISHAY_VLMB1300-GS08_BLUE_1A2K_H0P8 -0.762,18.669 r270 top value=Blue
LinU "Test_pin_conn_black - NOT CONNECTED" TP_PTH-1P02MM_TEST-TERMINAL_RS_101-2391_BLACK 18.034,133.731 r0 top value=20-2137
LinV "Test_pin_conn_black - NOT CONNECTED" TP_PTH-1P02MM_TEST-TERMINAL_RS_101-2391_BLACK 17.399,90.043 r0 top value=20-2137
LinW "Test_pin_conn_black - NOT CONNECTED" TP_PTH-1P02MM_TEST-TERMINAL_RS_101-2391_BLACK 16.764,51.181 r0 top value=20-2137
MB2017B "Comment" LOGO_ST 9.903,17.767 r0 top
NTC1 "MISC_NTC_NB20K00103JBA" NTC1206_AVX_NB20_H1P5 41.402,62.484 r270 top value=10K
OC_Bias "Test Point" TP_SMD_1MM 5.588,59.563 r180 top value="Test Point 1mm"
OV_Vcc "Test Point" TP_SMD_1MM -10.16,30.607 r180 top value="Test Point 1mm"
Overcurrent "Test_pin_conn_black - NOT CONNECTED" TP_PTH-1P02MM_TEST-TERMINAL_RS_101-2391_BLACK 81.915,17.399 r90 top value=20-2137
Q1 "PNP_SOT23" PNP_SOT23 25.931,124.649 r270 top value=FMMT718TA
Q2 "MOSFET_N-CHANNEL_INV" MOS_TO220-3_VERTICAL_H19P35 32.154,130.491 r270 top value=STP110N10F7
Q3 "MOSFET_N-CHANNEL_INV" MOS_TO220-3_VERTICAL_H19P35 32.154,119.442 r270 top value=STP110N10F7
Q4 "MOSFET_N-CHANNEL_INV" MOS_TO220-3_VERTICAL_H19P35 32.154,42.226 r270 top value=STP110N10F7
Q5 "MOSFET_N-CHANNEL_INV" MOS_TO220-3_VERTICAL_H19P35 50.315,42.226 r90 top value=STP110N10F7
Q6 "MOSFET_N-CHANNEL_INV" MOS_TO220-3_VERTICAL_H19P35 50.315,130.491 r90 top value=STP110N10F7
Q7 "MOSFET_N-CHANNEL_INV" MOS_TO220-3_VERTICAL_H19P35 50.315,119.442 r90 top value=STP110N10F7
Q8 "MOSFET_N-CHANNEL_INV" MOS_TO220-3_VERTICAL_H19P35 32.154,53.148 r270 top value=STP110N10F7
Q9 "MOSFET_N-CHANNEL_INV" MOS_TO220-3_VERTICAL_H19P35 50.315,53.148 r90 top value=STP110N10F7
Q10 "PNP_SOT23" PNP_SOT23 25.908,48.133 r270 top value=FMMT718TA
Q11 "PNP_SOT23" PNP_SOT23 34.671,34.036 r270 top value=FMMT718TA
Q12 "PNP_SOT23" PNP_SOT23 30.945,111.44 r270 top value=FMMT718TA
Q13 "PNP_SOT23" PNP_SOT23 25.931,86.422 r270 top value=FMMT718TA
Q14 "MOSFET_N-CHANNEL_INV" MOS_TO220-3_VERTICAL_H19P35 32.154,91.502 r270 top value=STP110N10F7
Q15 "MOSFET_N-CHANNEL_INV" MOS_TO220-3_VERTICAL_H19P35 32.154,80.453 r270 top value=STP110N10F7
Q16 "MOSFET_N-CHANNEL_INV" MOS_TO220-3_VERTICAL_H19P35 50.315,91.502 r90 top value=STP110N10F7
Q17 "MOSFET_N-CHANNEL_INV" MOS_TO220-3_VERTICAL_H19P35 50.315,80.453 r90 top value=STP110N10F7
Q18 "PNP_SOT23" PNP_SOT23 31.072,72.959 r270 top value=FMMT718TA
R1 "Resistor" R0603 -25.146,148.528 r90 top value=1K
R2 "Resistor" R0603 -36.895,149.352 r180 top value=470K
R3 "Resistor" R0603 -26.735,150.876 r180 top value=100K
R4 "Resistor" R0805 -30.988,133.745 r270 top value=1K5
R5 "Resistor" R0603 -34.544,150.049 r270 top value=49K9
R6 "Resistor" R0805 0.635,145.401 r90 top value=4K7
R7 "Resistor" R0603 -33.909,114.427 r90 top value=100R
R8 "Resistor" R0603_H0P45 -32.893,104.459 r270 top value=499K
R9 "Resistor" R0805 -32.639,96.125 r270 top value=470R
R10 "Resistor" R0603 -32.831,110.49 r180 top value=82K
R11 "Resistor" R0805 -25.527,75.565 r180 top value=470R
R12 "Resistor" R0805_H0P5 -5.715,17.653 r0 top value=10R
R13 "Resistor" R0805 -2.54,22.606 r90 top value=470R
R14 "Resistor" R0603 46.863,18.223 r270 top value=10K
R15 "Resistor" R0603 41.275,62.8 r270 bottom value=10K
R16 "Resistor" R0603 48.387,19.685 r270 top value=22K
R17 "Resistor" R0603 41.148,15.494 r90 top value=47K
R18 "Resistor" R0805_H0P5 80.264,120.015 r180 top value=6.8K
R19 "Resistor" R0805_H0P5 81.026,67.183 r180 top value=6.8K
R20 "Resistor" R0805_H0P5 80.772,39.751 r180 top value=6.8K
R21 "Resistor" R0805 88.011,120.015 r180 top value=0R
R22 "Resistor" R0805 88.265,67.183 r180 top value=0R
R23 "Resistor" R0805 88.646,39.751 r180 top value=0R
R24 "Resistor" R0603_H0P45 85.217,115.062 r180 top value=2K
R25 "Resistor" R0603_H0P45 83.439,120.015 r180 top value=2K
R26 "Resistor" R0603_H0P45 86.233,61.849 r180 top value=2K
R27 "Resistor" R0603_H0P45 84.709,67.183 r180 top value=2K
R28 "Resistor" R0603_H0P45 86.233,34.671 r180 top value=2K
R29 "Resistor" R0603_H0P45 84.709,39.751 r180 top value=2K
R30 "Resistor" R0805 73.787,14.591 r90 top value=0R
R31 "Resistor" R0805 72.136,14.591 r90 top value=0R
R32 "Resistor" R0805 70.485,14.619 r90 top value=0R
R33 "Resistor" R0805 68.834,14.619 r270 top value=0R
R34 "Resistor" R0805 62.23,14.605 r90 top value=0R
R35 "Resistor" R0805 65.532,14.605 r270 top value=0R
R36 "Resistor" R0805 77.089,22.225 r90 top value=0R
R37 "Resistor" R0805 58.928,14.605 r90 top value=0R
R38 "Resistor" R0805 67.183,14.605 r270 top value=0R
R39 "Resistor" R0805 75.438,22.225 r90 top value=0R
R40 "Resistor" R0805 60.579,14.605 r90 top value=0R
R41 "Resistor" R0805 63.881,14.605 r270 top value=0R
R42 "Resistor" R0805 73.787,22.225 r90 top value=0R
R43 "Resistor" R0805 72.136,22.211 r90 top value=0R
R44 "Resistor" R0603 78.74,21.971 r270 top value=100K
R45 "Resistor" R0805 70.485,22.225 r90 top value=0R
R46 "Resistor" R0805 68.834,22.225 r270 top value=0R
R47 "Resistor" R0805 55.88,14.097 r270 top value=0R
R48 "Resistor" R0805 52.578,14.097 r90 top value=0R
R49 "Resistor" R0805 54.229,14.097 r270 top value=0R
R50 "Resistor" R0805 55.88,21.717 r90 top value=0R
R51 "Resistor" R0805 54.229,21.717 r270 top value=0R
R52 "Resistor" R0805 50.927,14.083 r90 top value=0R
R53 "Resistor" R0603 8.636,135.509 r270 top value=1K
R54 "Resistor" R0603 19.558,93.091 r90 top value=1K
R55 "Resistor" R0603 20.955,133.096 r270 top value=1K
R56 "Resistor" R0603 8.636,53.975 r90 top value=1K
R57 "Resistor" R0603 17.399,55.245 r180 top value=1K
R58 "Resistor" R0603 14.732,90.043 r90 top value=1K
R59 "Resistor" R0805 21.98,125.665 r180 top value=10R
R60 "Resistor" R0805 22.008,123.76 r180 top value=10R
R61 "Resistor" R0805 16.764,123.43 r270 top value=10R
R62 "Resistor" R0805_H0P6 28.979,133.92 r0 top value=4R7
R63 "Resistor" R0805_H0P6 28.965,121.982 r0 top value=4R7
R64 "Resistor" R0805_H0P5 28.979,126.681 r180 top value=22K
R65 "Resistor" R0805_H0P6 28.725,45.02 r0 top value=4R7
R66 "Resistor" R0805_H0P6 53.617,38.035 r180 top value=4R7
R67 "Resistor" R0805_H0P5 53.744,46.036 r180 top value=22K
R68 "Resistor" R0603 13.716,129.351 r90 top value=100R
R69 "Resistor" R0805_H0P5 28.725,49.592 r0 top value=22K
R70 "Resistor" R0805_H0P6 53.476,127.951 r180 top value=4R7
R71 "Resistor" R0805_H0P6 53.49,115.124 r180 top value=4R7
R72 "Resistor" R0603 15.556,128.905 r0 top value=100R
R73 "Resistor" R0805_H0P5 53.49,122.744 r180 top value=22K
R74 "Resistor" R0603 3.367,123.19 r0 top value=6K8
R75 "Resistor" R0805_H0P6 28.725,57.085 r0 top value=4R7
R76 "Resistor" R0805_H0P6 53.73,50.608 r180 top value=4R7
R77 "Resistor" R0603 3.429,118.491 r90 top value=680R
R78 "Resistor" R0805 22.239,47.244 r180 top value=10R
R79 "Resistor" R0603 3.937,36.576 r90 top value=680R
R80 "Resistor" R0603_H0P45 5.334,35.179 r90 top value=3k6
R81 "Resistor" R0603_H0P45 5.08,117.029 r90 top value=3k6
R82 "Resistor" R0603 10.922,134.112 r270 top value=1K
R83 "Resistor" R0805 27.305,112.395 r180 top value=10R
R84 "Resistor" R0805 30.734,32.893 r180 top value=10R
R85 "Resistor" R0805 27.305,110.49 r180 top value=10R
R86 "Resistor" R0805 22.239,49.022 r180 top value=10R
R87 "Resistor" R0805 30.748,34.925 r180 top value=10R
R88 "Resistor" R0805 22.516,87.438 r180 top value=10R
R89 "Resistor" R0805 22.516,85.533 r180 top value=10R
R90 "Resistor" R0805 16.764,79.502 r270 top value=10R
R91 "Resistor" R0805 16.764,40.386 r270 top value=10R
R92 "Resistor" R0805_H0P6 28.852,95.058 r0 top value=4R7
R93 "Resistor" R0805_H0P6 28.852,83.628 r0 top value=4R7
R94 "Resistor" R0805_H0P5 28.852,88.073 r180 top value=22K
R95 "Resistor" R0603 13.208,85.536 r90 top value=100R
R96 "Resistor" R0603 3.237,41.656 r180 top value=6K8
R97 "Resistor" R0805_H0P6 53.603,88.962 r180 top value=4R7
R98 "Resistor" R0805_H0P6 53.617,76.262 r180 top value=4R7
R99 "Resistor" R0603 15.178,85.344 r0 top value=100R
R100 "Resistor" R0805_H0P5 53.617,84.009 r180 top value=22K
R101 "Resistor" R0603 3.175,79.756 r0 top value=6K8
R102 "Resistor" R0603 3.683,74.611 r90 top value=680R
R103 "Resistor" R0603 10.414,52.705 r270 top value=1K
R104 "Resistor" R0603 12.954,47.498 r90 top value=100R
R105 "Resistor" R0603 15.113,46.99 r0 top value=100R
R106 "Resistor" R0603_H0P45 5.207,73.341 r90 top value=3k6
R107 "Resistor" R0603 10.668,90.108 r270 top value=1K
R108 "Resistor" R0805 27.643,73.975 r180 top value=10R
R109 "Resistor" R0805 27.643,71.943 r180 top value=10R
R110 "Resistor" R0603 9.398,59.628 r90 top value=13K
R111 "Resistor" R0603 6.604,61.784 r270 top value=22K
R112 "Resistor" R0603 6.604,64.2 r270 top value=330R
R113 "Resistor" R0603 0.762,64.262 r90 top value=300R
R114 "Resistor" R0603 90.297,133.604 r90 top value=220K
R115 "Resistor" R0603 80.329,129.413 r180 top value=75K
R116 "Resistor" R0603 91.186,131.318 r0 top value=10R
R117 "Resistor" R0603 83.312,129.413 r180 top value=11K
R118 "Resistor" R0805_H0P5 87.122,125.476 r90 top value=9K31
R119 "Resistor" R0603_H0P45 -13.527,38.608 r0 top value=2K8
R120 "Resistor" R0603 4.318,53.148 r90 top value=169K
R121 "Resistor" R0603 -10.16,32.893 r270 top value=100R
R122 "Resistor" R0603 90.424,80.518 r90 top value=220K
R123 "Resistor" R0603 80.899,77.47 r180 top value=75K
R124 "Resistor" R0603 4.318,49.784 r90 top value=10K
R125 "Resistor" R0603 -3.302,51.308 r90 top value=10K
R126 "Resistor" R0603 -13.97,36.641 r90 top value=13K
R127 "Resistor" R0603 91.186,78.359 r0 top value=10R
R128 "Resistor" R0603 11.43,96.266 r180 bottom value=220R
R129 "Resistor" R0603 -16.637,36.703 r270 top value=0R
R130 "Resistor" R0603 83.439,77.47 r180 top value=11K
R131 "Resistor" R0805_H0P5 86.36,72.517 r90 top value=9K31
R132 "Resistor" R0603 91.059,52.894 r90 top value=220K
R133 "Resistor" R0603 80.899,49.784 r180 top value=75K
R134 "Resistor" R0603 91.313,50.419 r0 top value=10R
R135 "Resistor" R0603_H0P45 90.805,92.837 r90 top value=10K
R136 "Resistor" R0603 84.074,49.784 r180 top value=11K
R137 "Resistor" R0805_H0P5 86.868,44.591 r90 top value=9K31
R138 "Resistor" R0603 100.203,91.186 r270 top value=100R
R139 "Resistor" R0603_H0P45 90.805,90.297 r90 top value=10K
R140 "Resistor" R0603 -37.005,73.199 r90 top value=2K2
R141 "Resistor" R0603 -35.179,73.152 r90 top value=2K2
R142 "Resistor" R0603 -33.401,73.214 r90 top value=2K2
R143 "Resistor" R0603 38.862,33.528 r90 top value=169K
R144 "Resistor" R0603 45.212,32.131 r0 top value=10R
R145 "Resistor" R0805_H0P5 62.611,137.795 r90 top value=10R
R146 "Resistor" R0603 69.215,141.767 r270 top value=10K
R147 "Resistor" R0603_H0P45 -37.084,58.485 r90 top value=4K22
R148 "Resistor" R0603_H0P45 -35.179,58.485 r90 top value=4K22
R149 "Resistor" R0603_H0P45 -33.401,58.42 r90 top value=4K22
R150 "Resistor" R0603 38.862,30.861 r90 top value=11K
R151 "Resistor" R0805_H0P5 40.527,25.273 r180 top value=9K31
R152 "Resistor" R0603 64.516,137.603 r90 top value=10R
R153 "Resistor" R0603 67.818,141.705 r90 top value=560R
R154 "Resistor" R0603 60.833,144.337 r270 top value=10R
R155 "Resistor" R0805 60.833,140.97 r90 top value=0R
R156 "Resistor" R0603 73.406,137.541 r90 top value=10R
R157 "Resistor" R0603 71.882,143.953 r90 top value=560R
R158 "Resistor" R0603 69.785,149.733 r180 top value=10K
R159 "Resistor" R0805_H0P5 75.057,137.809 r270 top value=10R
R160 "Resistor" R0603 -38.162,33.909 r0 top value=100R
R161 "Resistor" R0805_H0P5 62.484,100.443 r90 top value=10R
R162 "Resistor" R0603 68.961,104.202 r270 top value=10K
R163 "Resistor" R0805_H0P5 62.484,60.579 r90 top value=10R
R164 "Resistor" R0603 68.961,64.262 r270 top value=10K
R165 "Resistor" R0603 64.335,100.233 r90 top value=10R
R166 "Resistor" R0603 64.262,60.325 r90 top value=10R
R167 "Resistor" R0603 67.437,104.205 r90 top value=560R
R168 "Resistor" R0603 67.437,64.262 r90 top value=560R
R169 "Resistor" R0603 60.833,107.761 r270 top value=10R
R170 "Resistor" R0805 60.833,104.902 r90 top value=0R
R171 "Resistor" R0603 60.833,68.453 r270 top value=10R
R172 "Resistor" R0805 60.833,65.772 r90 top value=0R
R173 "Resistor" R0603 -36.703,44.639 r270 top value=10K
R174 "Resistor" R0603 73.406,100.203 r90 top value=10R
R175 "Resistor" R0603 71.882,106.807 r90 top value=560R
R176 "Resistor" R0603 73.406,60.325 r90 top value=10R
R177 "Resistor" R0603 72.009,67.629 r90 top value=560R
R178 "Resistor" R0603 -38.354,45.531 r90 top value=100R
R179 "Resistor" R0603 70.993,110.617 r180 top value=10K
R180 "Resistor" R0603 69.531,72.263 r180 top value=10K
R181 "Resistor" R0805_H0P5 75.184,100.33 r270 top value=10R
R182 "Resistor" R0805_H0P5 75.184,60.579 r270 top value=10R
R183 "Resistor" R0805 67.056,1.383 r270 bottom value=0R
R184 "Resistor" R0603 69.596,0.508 r180 bottom value=47K
RPW "RES_CSM4026Y" R4026_APR_CSM4026Y_Y14780R00100F9R 16.764,104.14 r0 top value=0R001
RSU "RES_CSM4026Y" R4026_APR_CSM4026Y_Y14780R00100F9R 68.961,132.207 r180 top value=0R001
RSV "RES_CSM4026Y" R4026_APR_CSM4026Y_Y14780R00100F9R 68.961,94.869 r180 top value=0R001
RSW "RES_CSM4026Y" R4026_APR_CSM4026Y_Y14780R00100F9R 68.834,54.991 r180 top value=0R001
RV1 "POTENTIOMETER" POT_BOURNS_3386P-1-101TLF 20.574,63.119 r270 top value=1K
RV2 "POTENTIOMETER" POT_BOURNS_3386P-1-101TLF -12.7,47.244 r0 top value=1K
ShuntU+ "Test_pin_conn_black - NOT CONNECTED" TP_PTH-1P02MM_TEST-TERMINAL_RS_101-2391_BLACK 61.595,148.209 r90 top value=20-2137
ShuntV+ "Test_pin_conn_black - NOT CONNECTED" TP_PTH-1P02MM_TEST-TERMINAL_RS_101-2391_BLACK 77.089,107.696 r90 top value=20-2137
ShuntW+ "Test_pin_conn_black - NOT CONNECTED" TP_PTH-1P02MM_TEST-TERMINAL_RS_101-2391_BLACK 76.835,69.596 r90 top value=20-2137
Temp "Test Point" TP_SMD_1MM 30.48,61.214 r180 top value="Test Point 1mm"
Throttle "Test Point" TP_SMD_1MM -32.004,31.496 r90 top value="Test Point 1mm"
TP1 "Test_pinX2" CON_JUMPER_HARWIN_S1621-46R -37.603,84.709 r180 top value=S1621-46R
TP2 "Test_pinX2" CON_JUMPER_HARWIN_S1621-46R 94.118,104.775 r180 top value=S1621-46R
TP3 "Test_pinX2" CON_JUMPER_HARWIN_S1621-46R 26.151,149.606 r180 top value=S1621-46R
TP4 "Test_pinX2" CON_JUMPER_HARWIN_S1621-46R -26.046,23.495 r180 top value=S1621-46R
TP5 "Test_pinX2" CON_JUMPER_HARWIN_S1621-46R 93.737,27.94 r180 top value=S1621-46R
TP6 "Test Point" TP_SMD_1MM -19.05,40.894 r270 top value="Test Point 1mm"
U1 "LM5164DDAT" ICC_SO8-EPAD_DDA_5X4_P127 -30.099,147.447 r90 top
U2 "IC_L6981NDR" ICC_SO8_5X4_P127 -37.592,112.814 r0 top value=L6981NDR
U3 "IC_KF50BD-TR" ICC_SO8_5X4_P127 -24.257,83.947 r0 top value=KF50BD-TR
U4 "ST730M33R" ICC_SOT23-5L_H1P45 -5.842,20.828 r180 top
U5 "IC_TS5A9411DCKR" MOS_SOT363-6L_SC-88_H1P10_P065 43.18,18.288 r0 top value=TS5A9411DCKR
U7 "IC_L6491DTR" ICC_SO14_8P75X6P20_P127_H1P75 9.271,122.047 r180 top value=L6491DTR
U8 "IC_L6491DTR" ICC_SO14_8P75X6P20_P127_H1P75 9.271,40.259 r180 top value=L6491DTR
U9 "IC_L6491DTR" ICC_SO14_8P75X6P20_P127_H1P75 9.271,78.486 r180 top value=L6491DTR
U10 "TS3021" AOP_SOT23-5L_H1P45 -11.303,36.068 r90 top value=TS3021ILT
U11 "TSC2020IST" ICC_MINISO8_3X3_P065 15.875,97.282 r90 bottom
U12 "TSV911ILT" AOP_SOT23-5L_H1P45 95.885,92.075 r270 top
U13 "TSV791ILT" ICC_SOT23-5L_H1P45 68.834,145.288 r0 top
U14 "TSV791ILT" ICC_SOT23-5L_H1P45 68.326,107.823 r0 top
U15 "TSV791ILT" ICC_SOT23-5L_H1P45 69.215,68.199 r0 top
VBAT "CON_M4_SNAP_IN_THR_KEYSTONE_7798" CON_KEYSTONE_M4-SNAP_7798 -8.763,144.78 r90 top value="TERM SCREW M4 PCB 30A"
Vcc_power "Test_pin_conn_black - NOT CONNECTED" TP_PTH-1P02MM_TEST-TERMINAL_RS_101-2391_BLACK 50.292,33.655 r90 top value=20-2137
Vcc_PW "Test_pin_conn_black - NOT CONNECTED" TP_PTH-1P02MM_TEST-TERMINAL_RS_101-2391_BLACK 50.292,26.416 r90 top value=20-2137
VoutU "CON_M4_SNAP_IN_THR_KEYSTONE_7798" CON_KEYSTONE_M4-SNAP_7798 65.913,119.959 r180 top value="TERM SCREW M4 PCB 30A"
VoutV "CON_M4_SNAP_IN_THR_KEYSTONE_7798" CON_KEYSTONE_M4-SNAP_7798 65.913,81.153 r180 top value="TERM SCREW M4 PCB 30A"
VoutW "CON_M4_SNAP_IN_THR_KEYSTONE_7798" CON_KEYSTONE_M4-SNAP_7798 65.936,42.226 r180 top value="TERM SCREW M4 PCB 30A"
VU "Test_pin_conn_black - NOT CONNECTED" TP_PTH-1P02MM_TEST-TERMINAL_RS_101-2391_BLACK 96.774,128.27 r0 top value=20-2137
VV "Test_pin_conn_black - NOT CONNECTED" TP_PTH-1P02MM_TEST-TERMINAL_RS_101-2391_BLACK 96.774,75.311 r0 top value=20-2137
VW "Test_pin_conn_black - NOT CONNECTED" TP_PTH-1P02MM_TEST-TERMINAL_RS_101-2391_BLACK 96.774,46.482 r0 top value=20-2137

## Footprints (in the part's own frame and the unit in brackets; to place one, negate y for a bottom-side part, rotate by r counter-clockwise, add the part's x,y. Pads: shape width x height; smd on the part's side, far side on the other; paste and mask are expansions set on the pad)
AOP_SOT23-5L_H1P45 [mm]
  rect 0.6x1.3 smd mask+0.05: 1(-0.95,-1.1) 2(0,-1.1) 3(0.95,-1.1) 4(0.95,1.1) 5(-0.95,1.1)
  silkscreen extent -1.75,-1.68 1.6,0.97, body extent -1.52,-1.25 1.52,1.25, height 1.45
C0603 [mm]
  rect 0.64x0.89 smd mask+0.05: 1(-0.7,0) 2(0.7,0)
  silkscreen extent -1.05,-0.55 1.02,0.55, body extent -0.9,-0.5 0.9,0.5, height 1.4
C0603_H0P8 [mm] "MCD-01540"
  rect 0.64x0.89 smd mask+0.05: 1(-0.7,0) 2(0.7,0)
  silkscreen extent -0.9,-0.55 0.9,0.55, body extent -0.9,-0.5 0.9,0.5, height 1
C0805 [mm]
  rect 0.9x1.4 smd mask+0.05: 1(-0.85,0) 2(0.85,0)
  silkscreen extent -1.3,-0.77 1.3,0.77, body extent -1.1,-0.7 1.1,0.7, height 1.35
C0805_H0P85 [mm] "MCD-01525"
  rect 0.9x1.4 smd mask+0.05: 1(-0.85,0) 2(0.85,0)
  silkscreen extent -1.3,-0.77 1.3,0.77, body extent -1.1,-0.73 1.1,0.73, height 0.95
C1206_H1P6 [mm]
  rect 1.4x1.78 smd mask+0.05: 1(-1.4,0) 2(1.4,0)
  silkscreen extent -2.12,-0.97 2.15,0.97, body extent -1.7,-0.9 1.7,0.9, height 1.8
C1206_H1P15 [mm]
  rect 1.4x1.78 smd mask+0.05: 1(-1.4,0) 2(1.4,0)
  silkscreen extent -2.12,-0.97 2.15,0.97, body extent -1.7,-0.9 1.7,0.9, height 1.35
C1206_H1P25 [mm]
  rect 1.4x1.78 smd mask+0.05: 1(-1.4,0) 2(1.4,0)
  silkscreen extent -2.12,-0.97 2.15,0.97, body extent -1.7,-0.9 1.7,0.9, height 1.45
CON_JUMPER_HARWIN_S1621-46R [mm] "MCD-03485"
  rect 2.4x2.8 smd mask+0.05: 1(-5.45,0) 2(5.45,0)
  silkscreen extent -4,-1.15 4,1.15, body extent -6.15,-1.15 6.15,1.15, height 1.8
CON_KEYSTONE_M4-SNAP_7798 [mm] "MCD-03715"
  round 3.6 hole 2 mask+0.05: 1(-5,-3.5) 1(-5,3.5) 1(0,3.5) 1(0,-3.5) 1(5,-3.5) 1(5,3.5)
  silkscreen extent -6.22,-4.06 6.35,4.19, body extent -6.44,-4.55 6.44,4.5, height 9.18
CON_SAMTEC_PCIE-164-02-X-D-RA [mm] "MCD-02664"
  rect 1.2x1.2 hole 0.7: A01(41.5,4.25)
  round 1.2 hole 0.7: A02(40.5,2.25) A03(39.5,4.25) A04(38.5,2.25) A05(37.5,4.25) A06(36.5,2.25) A07(35.5,4.25) A08(34.5,2.25) A09(33.5,4.25) A10(32.5,2.25) A11(31.5,4.25) A12(28.5,2.25) A13(27.5,4.25) A14(26.5,2.25) A15(25.5,4.25) A16(24.5,2.25) A17(23.5,4.25) A18(22.5,2.25) A19(21.5,4.25) A20(20.5,2.25) A21(19.5,4.25) A22(18.5,2.25) A23(17.5,4.25) A24(16.5,2.25) A25(15.5,4.25) A26(14.5,2.25) A27(13.5,4.25) A28(12.5,2.25) A29(11.5,4.25) A30(10.5,2.25) A31(9.5,4.25) A32(8.5,2.25) A33(7.5,4.25) A34(6.5,2.25) A35(5.5,4.25) A36(4.5,2.25) A37(3.5,4.25) A38(2.5,2.25) A39(1.5,4.25) A40(0.5,2.25) A41(-0.5,4.25) A42(-1.5,2.25) A43(-2.5,4.25) A44(-3.5,2.25) A45(-4.5,4.25) A46(-5.5,2.25) A47(-6.5,4.25) A48(-7.5,2.25) A49(-8.5,4.25) A50(-9.5,2.25) A51(-10.5,4.25) A52(-11.5,2.25) A53(-12.5,4.25) A54(-13.5,2.25) A55(-14.5,4.25) A56(-15.5,2.25) A57(-16.5,4.25) A58(-17.5,2.25) A59(-18.5,4.25) A60(-19.5,2.25) A61(-20.5,4.25) A62(-21.5,2.25) A63(-22.5,4.25) A64(-23.5,2.25) A65(-24.5,4.25) A66(-25.5,2.25) A67(-26.5,4.25) A68(-27.5,2.25) A69(-28.5,4.25) A70(-29.5,2.25) A71(-30.5,4.25) A72(-31.5,2.25) A73(-32.5,4.25) A74(-33.5,2.25) A75(-34.5,4.25) A76(-35.5,2.25) A77(-36.5,4.25) A78(-37.5,2.25) A79(-38.5,4.25) A80(-39.5,2.25) A81(-40.5,4.25) A82(-41.5,2.25) B01(41.5,6.75) B02(40.5,8.75) B03(39.5,6.75) B04(38.5,8.75) B05(37.5,6.75) B06(36.5,8.75) B07(35.5,6.75) B08(34.5,8.75) B09(33.5,6.75) B10(32.5,8.75) B11(31.5,6.75) B12(28.5,8.75) B13(27.5,6.75) B14(26.5,8.75) B15(25.5,6.75) B16(24.5,8.75) B17(23.5,6.75) B18(22.5,8.75) B19(21.5,6.75) B20(20.5,8.75) B21(19.5,6.75) B22(18.5,8.75) B23(17.5,6.75) B24(16.5,8.75) B25(15.5,6.75) B26(14.5,8.75) B27(13.5,6.75) B28(12.5,8.75) B29(11.5,6.75) B30(10.5,8.75) B31(9.5,6.75) B32(8.5,8.75) B33(7.5,6.75) B34(6.5,8.75) B35(5.5,6.75) B36(4.5,8.75) B37(3.5,6.75) B38(2.5,8.75) B39(1.5,6.75) B40(0.5,8.75) B41(-0.5,6.75) B42(-1.5,8.75) B43(-2.5,6.75) B44(-3.5,8.75) B45(-4.5,6.75) B46(-5.5,8.75) B47(-6.5,6.75) B48(-7.5,8.75) B49(-8.5,6.75) B50(-9.5,8.75) B51(-10.5,6.75) B52(-11.5,8.75) B53(-12.5,6.75) B54(-13.5,8.75) B55(-14.5,6.75) B56(-15.5,8.75) B57(-16.5,6.75) B58(-17.5,8.75) B59(-18.5,6.75) B60(-19.5,8.75) B61(-20.5,6.75) B62(-21.5,8.75) B63(-22.5,6.75) B64(-23.5,8.75) B65(-24.5,6.75) B66(-25.5,8.75) B67(-26.5,6.75) B68(-27.5,8.75) B69(-28.5,6.75) B70(-29.5,8.75) B71(-30.5,6.75) B72(-31.5,8.75) B73(-32.5,6.75) B74(-33.5,8.75) B75(-34.5,6.75) B76(-35.5,8.75) B77(-36.5,6.75) B78(-37.5,8.75) B79(-38.5,6.75) B80(-39.5,8.75) B81(-40.5,6.75) B82(-41.5,8.75)
  round 2.35 hole 2.35 unplated: ""(-43.3,-2.25) ""(29.85,-2.25)
  silkscreen extent -44.5,-9.8 44.5,9.8, body extent -44.51,-9.8 44.49,9.05, height 9.45
CON_SAMTEC_TSW-102-07-G-S [mm]
  rect 1.85x1.85 / inner round 1.85 / far side rect 1.85x1.85 hole 1 mask+0.05: 1(-1.27,0)
  round 1.85 hole 1 mask+0.05: 2(1.27,0)
  silkscreen extent -2.58,-1.3 2.58,1.3, body extent -2.67,-1.3 2.58,1.3, height 8.38
CON_SAMTEC_TSW-103-07-F-S [mm]
  rect 1.85x1.85 / inner round 1.85 / far side rect 1.85x1.85 hole 1 mask+0.05: 1(-2.54,0)
  round 1.85 hole 1 mask+0.05: 2(0,0) 3(2.54,0)
  silkscreen extent -3.85,-1.3 3.85,1.3, body extent -3.94,-1.37 3.91,1.37, height 8.38
CON_SAMTEC_TSW-105-07-X-S [mm] "MCD-02060"
  rect 1.85x1.85 hole 1 mask+0.05: 1(-5.08,0)
  round 1.85 hole 1 mask+0.05: 2(-2.54,0) 3(0,0) 4(2.54,0) 5(5.08,0)
  silkscreen extent -6.35,-1.27 6.35,1.27, body extent -6.48,-1.27 6.35,1.27, height 8.38
CPOL_TDK_B41858C9227M000_H25 [mm]
  rect 2x2 hole 1: 1(0,0)
  round 2 hole 1: 2(7.5,0)
  silkscreen extent -5.59,-8 11.81,8, body extent -4.44,-8.25 12.06,8.25, height 26.1
DIO_SMB_1K_2A [mm]
  rect 1.8x2.2 smd: 1(0,0) 2(4.22,0)
  silkscreen extent -1.65,-1.97 4.47,2.03, body extent -0.69,-1.98 4.89,1.98, height 2.64
DIO_SOT23 [mm]
  rect 1x1.4 smd mask+0.05: 1(-0.95,-1.1) 2(0.95,-1.1) 3(0,1.1)
  silkscreen extent -1.63,-0.82 1.63,0.82, body extent -1.56,-1.25 1.56,1.25, height 1.1
ICC_MINISO8_3X3_P065 [mm]
  rect 0.4x1.4 smd mask+0.05: 1(0.975,2.125) 2(0.325,2.125) 3(-0.325,2.125) 4(-0.975,2.125) 5(-0.975,-2.125) 6(-0.325,-2.125) 7(0.325,-2.125) 8(0.975,-2.125)
  silkscreen extent -1.6,-1.55 1.6,1.55, body extent -1.6,-2.58 1.6,2.58, height 1.11
ICC_SO8-EPAD_DDA_5X4_P127 [mm] "MCD-03695"
  rrect40% 0.6x1.55 smd mask+0.05: 1(-1.905,-2.7) 2(-0.635,-2.7) 3(0.635,-2.7) 4(1.905,-2.7) 5(1.905,2.7) 6(0.635,2.7) 7(-0.635,2.7) 8(-1.905,2.7)
  round 0.45 hole 0.2 mask+0.102: 9(-1.95,-0.65) 9(-1.95,0.65) 9(-0.65,-0.65) 9(-0.65,0.65) 9(0.65,-0.65) 9(0.65,0.65) 9(1.95,-0.65) 9(1.95,0.65)
  rrect10% 4.9x2.95 smd paste-10 mask+0.05: 9(0,0)
  silkscreen extent -2.73,-3.25 2.58,2, body extent -2.45,-3 2.45,3, height 1.7
ICC_SO8_5X4_P127 [mm]
  rect 0.7x1.75 smd mask+0.05: 1(-1.905,-2.375) 2(-0.635,-2.375) 3(0.635,-2.375) 4(1.905,-2.375) 5(1.905,2.375) 6(0.635,2.375) 7(-0.635,2.375) 8(-1.905,2.375)
  silkscreen extent -2.73,-3.25 2.58,2, body extent -2.57,-3 2.57,3, height 1.75
ICC_SO14_8P75X6P20_P127_H1P75 [mm] "MCD-03383"
  rect 0.6x1.55 smd mask+0.05: 1(-3.81,-2.7) 2(-2.54,-2.7) 3(-1.27,-2.7) 4(0,-2.7) 5(1.27,-2.7) 6(2.54,-2.7) 7(3.81,-2.7) 8(3.81,2.7) 9(2.54,2.7) 10(1.27,2.7) 11(0,2.7) 12(-1.27,2.7) 13(-2.54,2.7) 14(-3.81,2.7)
  silkscreen extent -4.37,-1.95 4.37,1.95, body extent -4.4,-3 4.4,3, height 1.7
ICC_SOT23-5L_H1P45 [mm]
  rect 0.6x1.3 smd mask+0.05: 1(-0.95,-1.1) 2(0,-1.1) 3(0.95,-1.1) 4(0.95,1.1) 5(-0.95,1.1)
  silkscreen extent -1.75,-1.68 1.6,0.97, body extent -1.52,-1.25 1.52,1.25, height 1.45
IND_COILCRAFT_MSS1038T-333MLC [mm] "MCD-03623"
  rect 3.56x1.78 smd mask+0.05: 1(0,4.7) 2(0,-4.7)
  silkscreen extent -5.1,-5.25 5.1,5.25, body extent -5.1,-5.15 5.1,5.15, height 4
IND_WURTH_7447714680 [mm]
  rect 2x3.5 smd: 1(-0.055,0) 2(9,0)
  silkscreen extent -1.4,-5.97 10.29,5.97, body extent -0.56,-5.08 9.45,4.92, height 4.8
LED_0603_VISHAY_VLMB1300-GS08_BLUE_1A2K_H0P8 [mm]
  rect 0.8x0.8 smd mask+0.05: 1(-0.75,0) 2(0.75,0)
  silkscreen extent -0.85,-0.53 1.28,0.53, body extent -0.85,-0.45 0.85,0.45, height 0.8
LED_0603_VISHAY_VLMO1300-GS08_ORANGE_1A2K_H0P8 [mm]
  rect 0.8x0.8 smd mask+0.05: 1(-0.75,0) 2(0.75,0)
  silkscreen extent -0.85,-0.53 1.28,0.53, body extent -0.85,-0.45 0.85,0.45, height 0.8
LED_0603_VISHAY_VLMS1300-GS08_RED_1A2K_H0P8 [mm]
  rect 0.8x0.8 smd mask+0.05: 1(-0.75,0) 2(0.75,0)
  silkscreen extent -0.85,-0.53 1.28,0.53, body extent -0.85,-0.45 0.85,0.45, height 0.8
LED_0603_VISHAY_VLMTG1300-GS08_GREEN_1A2K_H0P8 [mm]
  rect 0.8x0.8 smd mask+0.05: 1(-0.75,0) 2(0.75,0)
  silkscreen extent -0.85,-0.53 1.28,0.53, body extent -0.85,-0.45 0.85,0.45, height 0.8
LOGO_ST [mm]
  silkscreen extent -6.18,-2.95 5.25,3.14
MISC_Fischer_Elektronik_SK664100SA [mm]
  round 6 hole 3.5: 0(0,0) 0(25,0) 0(55,0) 0(80,0)
  silkscreen extent -10.03,-8.38 89.79,8.51, body extent -10.13,-20.07 90,20.07, height 60
MISC_JUMPER_1206_H0P55 [mm] "MCD-03351"
  rect 1x1.9 smd mask+0.05: 1(-1.3,0) 2(1.3,0)
  silkscreen extent -0.67,-0.85 0.67,0.85, body extent -1.6,-0.85 1.6,0.85, height 0.65
MOS_SOT363-6L_SC-88_H1P10_P065 [mm] "MCD-02143"
  rect 0.6x0.6 smd mask+0.05: 1(-0.75,-0.9) 3(0.75,-0.9) 4(0.75,0.9) 6(-0.75,0.9)
  rect 0.4x0.6 smd mask+0.05: 2(0,-0.9) 5(0,0.9)
  silkscreen extent -1.2,-1.33 1.1,0.48, body extent -1.1,-1.2 1.1,1.2, height 1.1
MOS_TO220-3_VERTICAL_H19P35 [mm] "MCD-03382"
  rect 2.4x2.4 hole 1.2 paste-2539.97 mask+0.05: 1(-2.54,0)
  oval 2x2.4 hole 1.2 paste-2539.97 mask+0.05: 2(0,0) 3(2.54,0)
  silkscreen extent -5.2,-1.53 5.2,3.07, body extent -4.95,-1.53 4.95,2.93, height 20.59
NTC1206_AVX_NB20_H1P5 [mm] "MCD-03782"
  rect 1x2.5 smd mask+0.05: 1(-1.5,0) 2(1.5,0)
  silkscreen extent -0.85,-0.8 0.85,0.8, body extent -1.64,-0.8 1.64,0.8, height 1.6
PNP_SOT23 [mm] "MCD-03327"
  rect 1x1.4 smd mask+0.05: 1(-0.95,-1.1) 2(0.95,-1.1) 3(0,1.1)
  silkscreen extent -1.63,-0.82 1.63,0.82, body extent -1.56,-1.25 1.56,1.25, height 1.1
POT_BOURNS_3386P-1-101TLF [mm] "MCD-02026"
  rect 1.7x1.7 hole 0.8 mask+0.05: 1(-2.54,0.02)
  round 1.7 hole 0.8 mask+0.05: 2(0,-2.52) 3(2.54,0.02)
  silkscreen extent -4.8,-4.8 4.8,4.8, body extent -4.8,-4.8 4.8,5.04, height 10.42
R0603 [mm]
  rect 0.64x1 smd mask+0.05: 1(-0.7,0) 2(0.7,0)
  silkscreen extent -1.05,-0.58 1.05,0.58, body extent -0.9,-0.5 0.9,0.5, height 0.56
R0603_H0P45 [mm]
  rect 0.64x1 smd mask+0.05: 1(-0.7,0) 2(0.7,0)
  silkscreen extent -1.05,-0.58 1.05,0.58, body extent -0.9,-0.5 0.9,0.5, height 0.56
R0805 [mm]
  rect 0.85x1.3 smd mask+0.05: 1(-0.875,0) 2(0.875,0)
  silkscreen extent -0.33,-0.67 0.33,0.67, body extent -1.05,-0.68 1.05,0.68, height 0.65
R0805_H0P5 [mm] "MCD-01537"
  rect 0.85x1.3 smd mask+0.05: 1(-0.875,0) 2(0.875,0)
  silkscreen extent -0.33,-0.67 0.33,0.67, body extent -1.05,-0.68 1.05,0.68, height 0.6
R0805_H0P6 [mm] "MCD-03338"
  rect 0.85x1.3 smd mask+0.05: 1(-0.875,0) 2(0.875,0)
  silkscreen extent -0.33,-0.67 0.33,0.67, body extent -1.05,-0.68 1.05,0.68, height 0.7
R4026_APR_CSM4026Y_Y14780R00100F9R [mm] "MCD-03392"
  rect 4x5.6 smd mask+0.05: F1(-4.75,0.85) F2(4.75,0.85)
  rect 4x0.9 smd mask+0.05: S1(-4.75,-3) S2(4.75,-3)
  silkscreen extent -2.44,-3.45 2.44,3.45, body extent -6.3,-3.45 6.3,3.45, height 3.5
TP_PTH-1P02MM_TEST-TERMINAL_RS_101-2391_BLACK [mm] "MCD-00713"
  round 3 hole 1.1 mask+0.05: 1(0,0)
  silkscreen extent -1.63,-1.62 1.63,1.62, body extent -1.24,-1.25 1.25,1.25, height 4.85
TP_SMD_1MM [mm]
  round 1 smd paste-10 mask+0.05: 1(0,0)
  silkscreen extent -0.7,-0.7 0.7,0.7

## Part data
3V3 5V 6V 12V5 Bias Brake_Levers GHU GHV GHW GLU GLV GLW H1 H2 H3 IoutU+ IoutV+ IoutW+ OC_Bias OV_Vcc Temp Throttle TP6: library part MCD-00074, "Test Point 1mm", Manufacturer=N/A, Manufacturer_HQ_COO=Unknown
C1: library part MCD-02457, "Capacitor, MLCC, 2.2nF, 50V, C0G/NPO, +/-5%, 0603, T=0,8mm", Manufacturer=YAGEO, Manufacturer_Part_Number=CC0603JRNPO9BN222, Package=0603
C2 C54 C55 C56: library part MCD-03694, "Capacitor, Aluminum Electrolytic Low ESR, 220uF, 100V, 0.099Ohms, +/-20%, 16x25mm, T=25mm", Manufacturer=TDK, Manufacturer_Part_Number=B41858C9227M000, Package=16x25mm
C3 C31 C32 C34 C35 C51 C57 C58: library part MCD-03394, "Capacitor, MLCC, 1uF, 100V, X7R, 10%, 1206, T=1.6mm", Manufacturer=TDK, Manufacturer_Part_Number=C3216X7R2A105K160AA, Package=1206
C4: library part MCD-01517, "Capacitor, MLCC, 47uF, 25V, X5R, +/-20%, 1206, T=1.6mm", Manufacturer=TDK, Manufacturer_Part_Number=C3216X5R1E476M160AC, Package=1206
C5 C10 C14 C15 C16 C17 C18 C77 C78 C86 C91 C92 C98 C111 C113 C126 C127 C128: library part MCD-01550, "Capacitor, MLCC, 1uF, 16V, X5R, +/-10%, 0805, T=0.85mm", Manufacturer=YAGEO, Manufacturer_Part_Number=CC0805KRX5R7BB105, Package=0805
C6 C8 C12 C13: library part MCD-02610, "Capacitor, MLCC, 10uF, 25V, X5R, +/-10%, 1206, T=1.6mm", Manufacturer=YAGEO, Manufacturer_Part_Number=CC1206KKX5R8BB106, Package=1206
C7 C38 C39 C48 C60 C61 C65: library part MCD-01525, "Capacitor, MLCC, 100nF, 50V, X7R, +/-10%, 0805, T=0.85mm", Manufacturer=YAGEO, Manufacturer_Part_Number=CC0805KRX7R9BB104, Package=0805
C9: library part MCD-02328, "Capacitor, MLCC, 22uF, 25V, X5R, +/-10%, 1206, T=1,6mm", Manufacturer="SAMSUNG ELECTRO-MECHANICS", Manufacturer_Part_Number=CL31A226KAHNNNE, Package=1206
C11 C22 C23 C24 C97 C106 C114 C115 C122 C123: library part MCD-00637, "Capacitor, MLCC, 10pF, 50V, NPO, +/-5%, 0603, T=0.8mm", Manufacturer=YAGEO, Manufacturer_Part_Number=CC0603JRNPO9BN100, Package=0603
C19 C20: library part MCD-01049, "Capacitor, MLCC, 4.7nF, 100V, X7R, +/-10%, 0603, T=1mm", Manufacturer=AVX, Manufacturer_Part_Number=06031C472K4T2A, Package=0603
